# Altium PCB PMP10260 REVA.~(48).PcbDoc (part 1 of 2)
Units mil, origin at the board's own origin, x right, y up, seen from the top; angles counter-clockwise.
Board outline 5118.11 x 4724.41 mil, 4 copper layers (Top Layer, MidLayer1, MidLayer2, Bottom Layer), stack 63.8 mil thick; 175 components, 80 nets, 424 pads, 447 vias.
Unrouted connection lines stored in the file: 1.
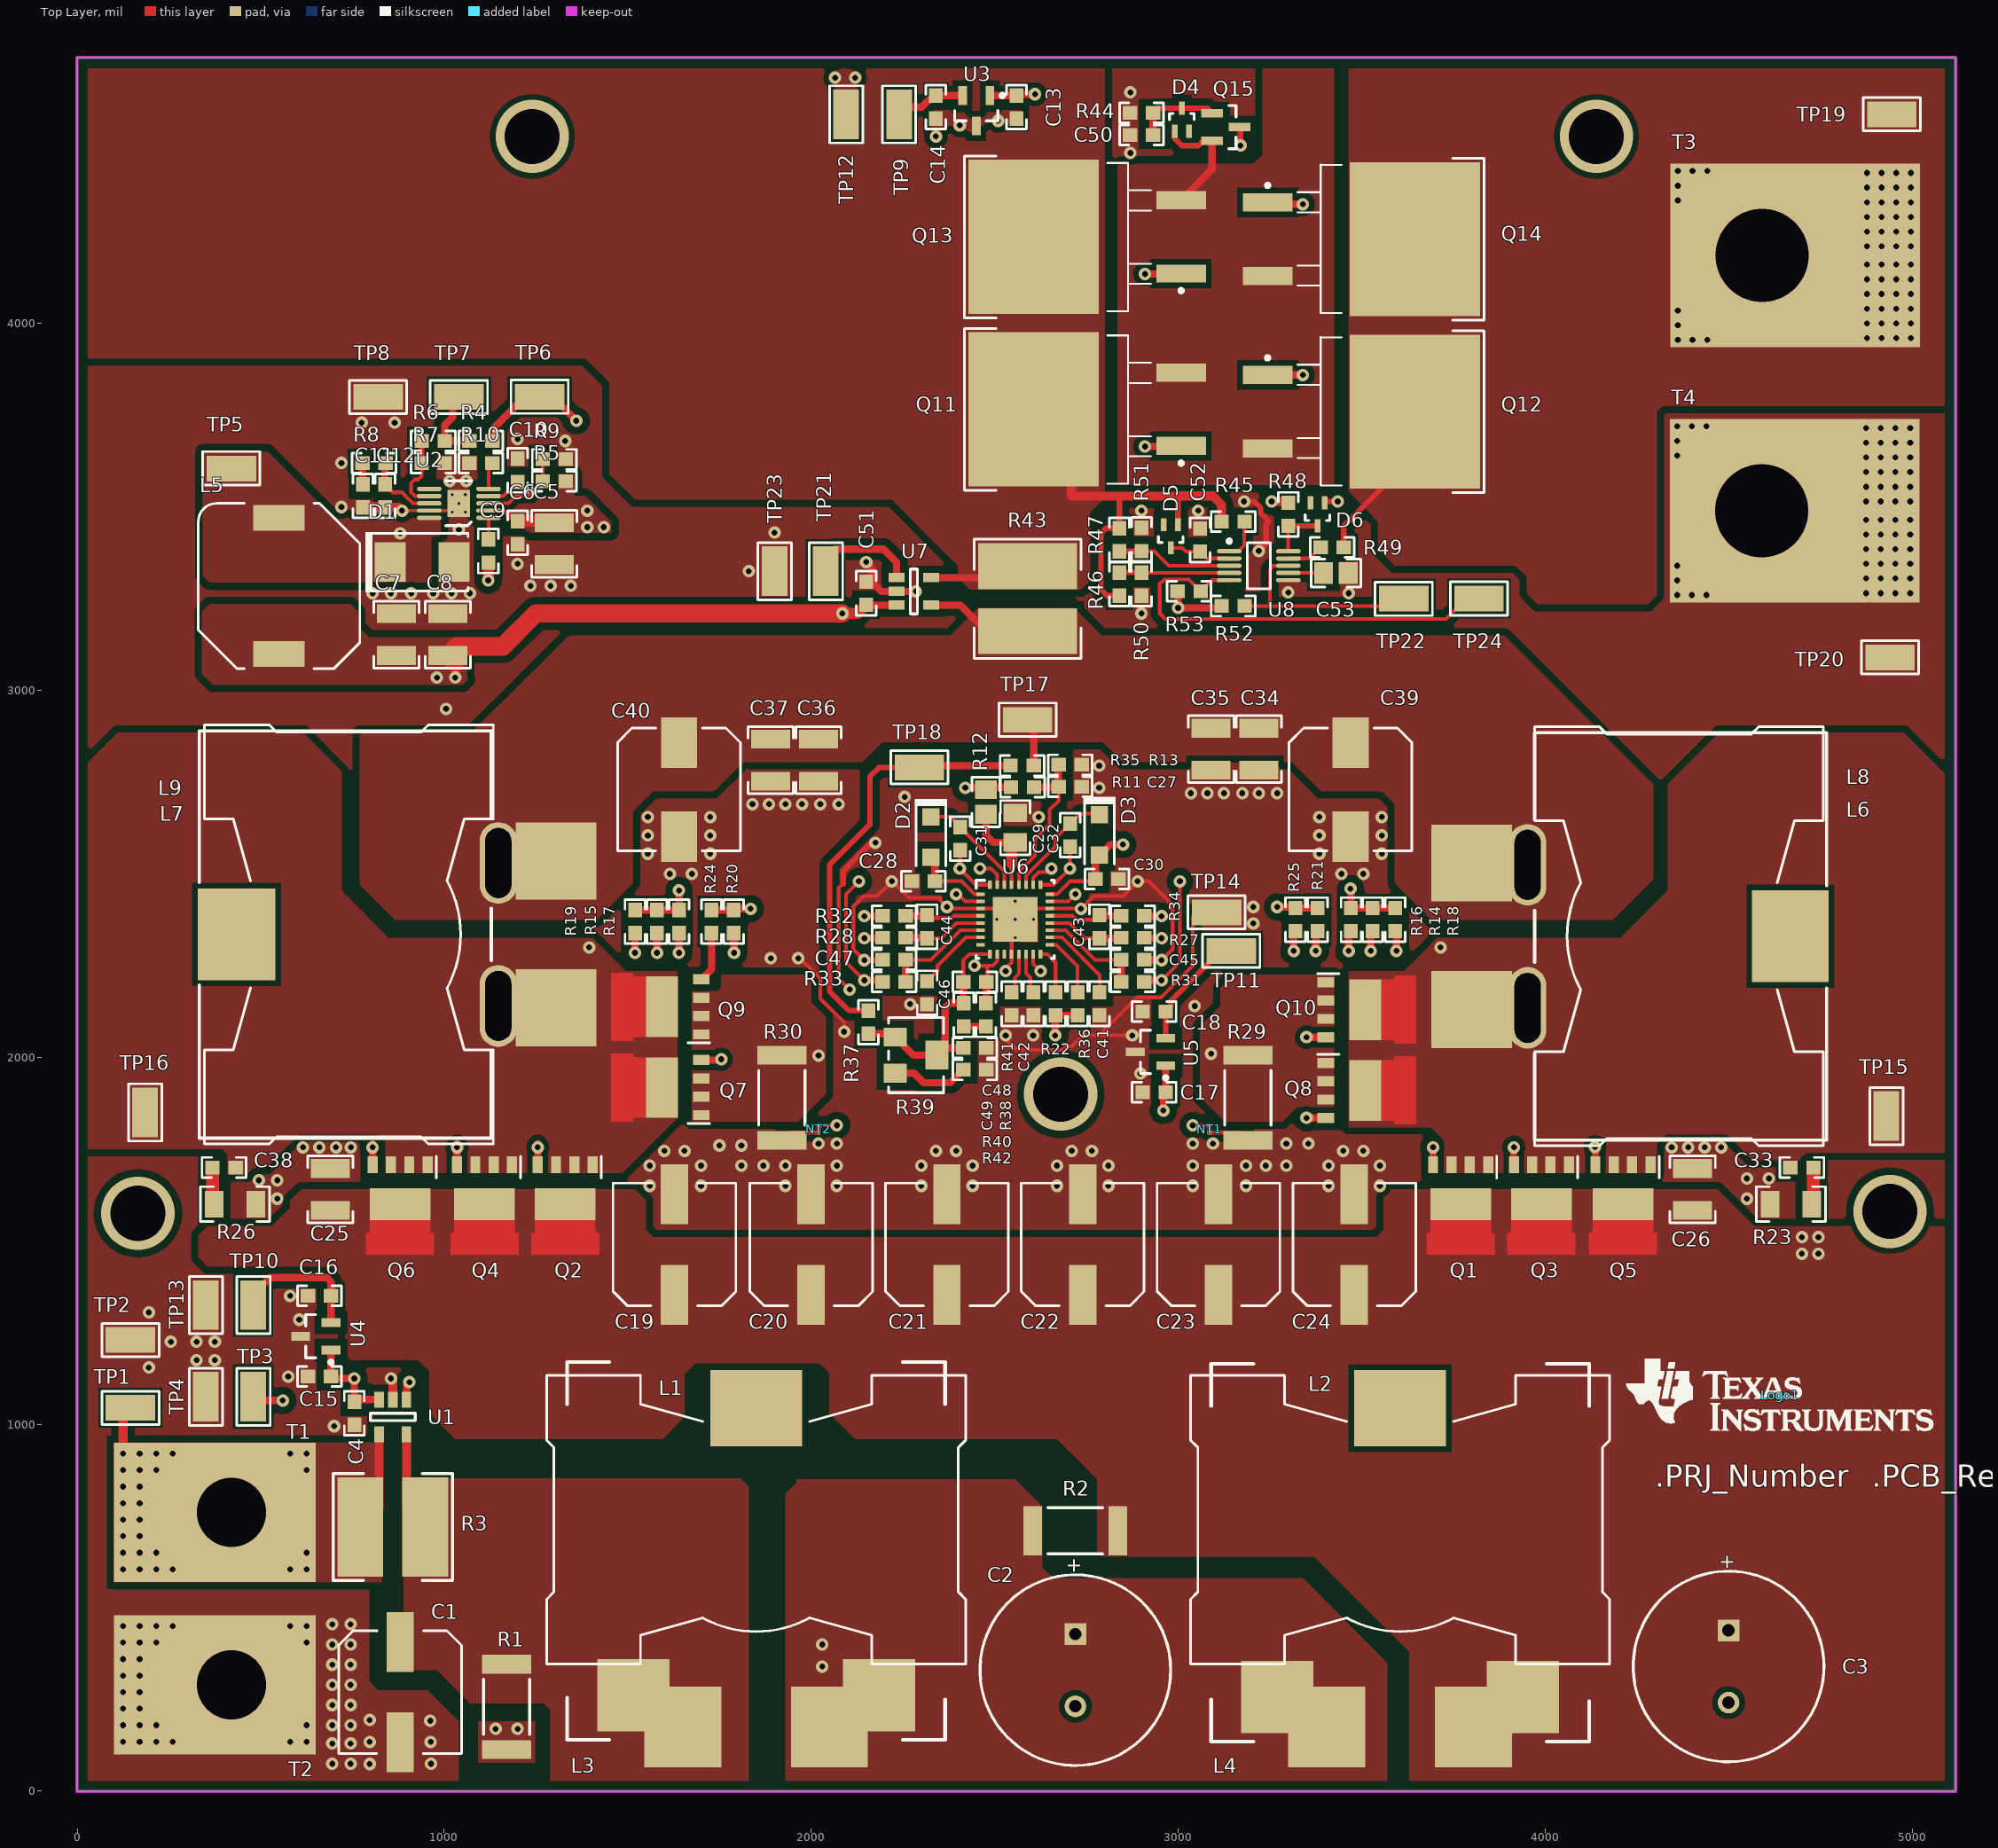
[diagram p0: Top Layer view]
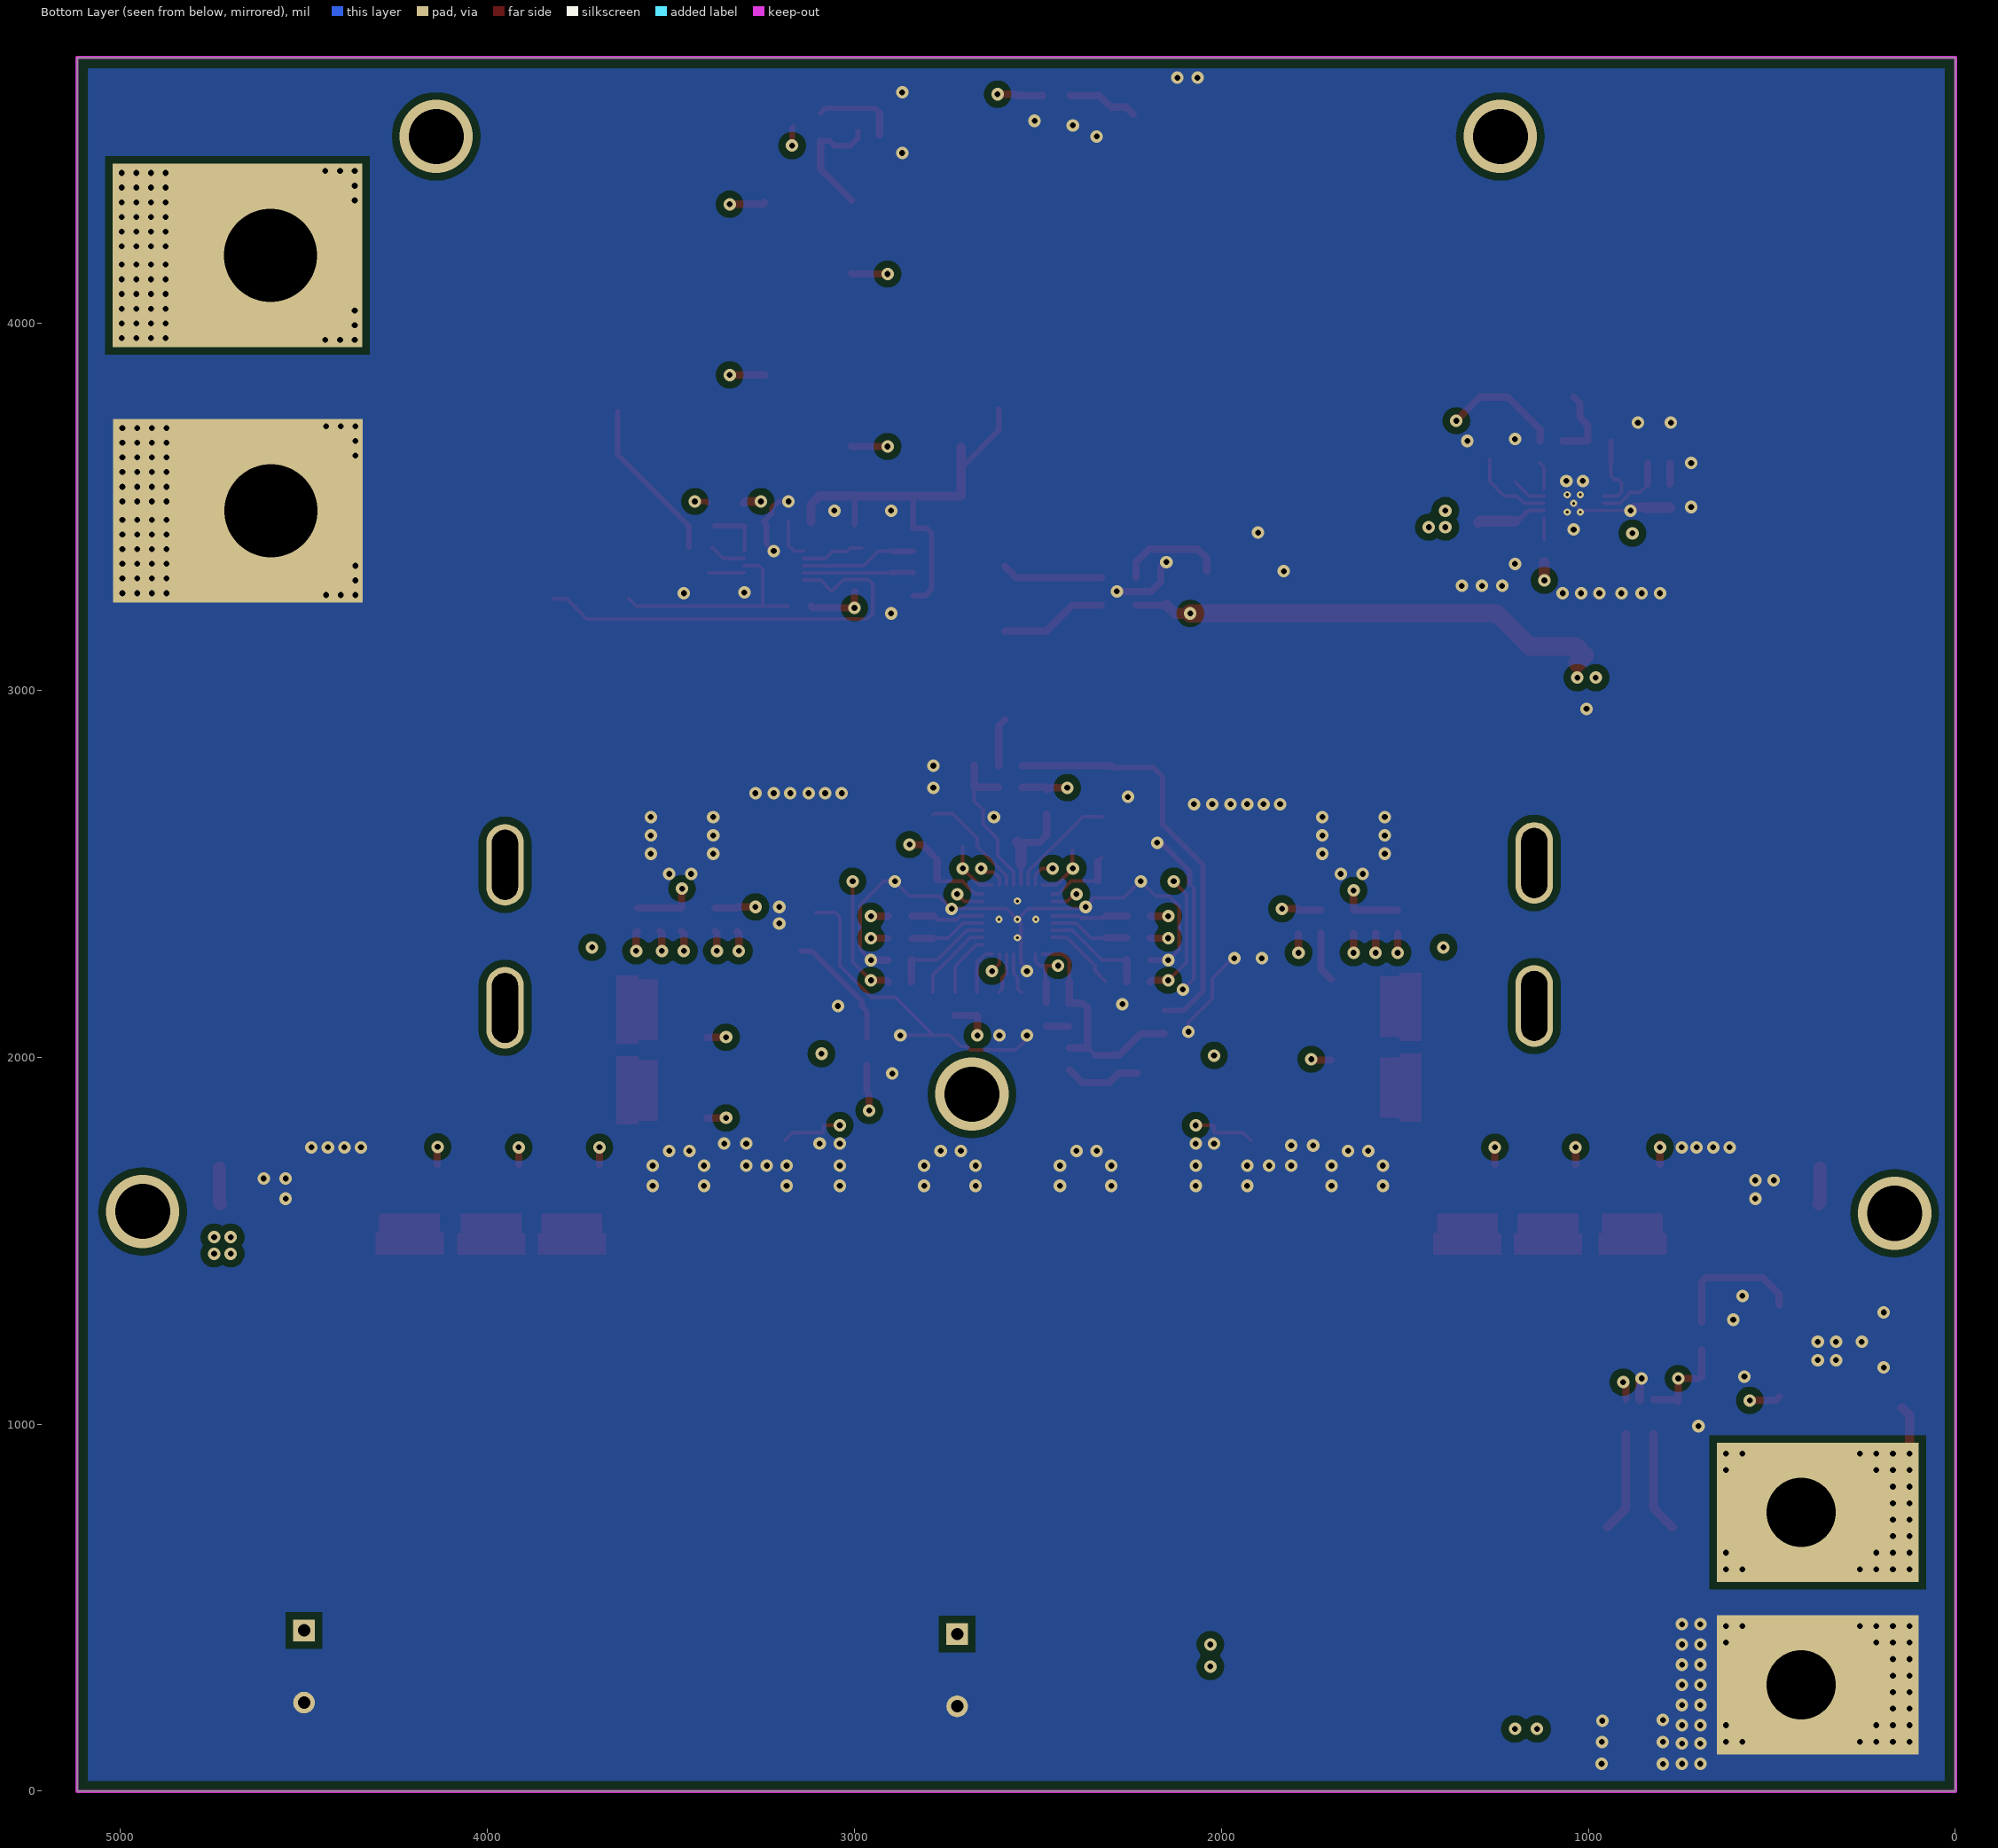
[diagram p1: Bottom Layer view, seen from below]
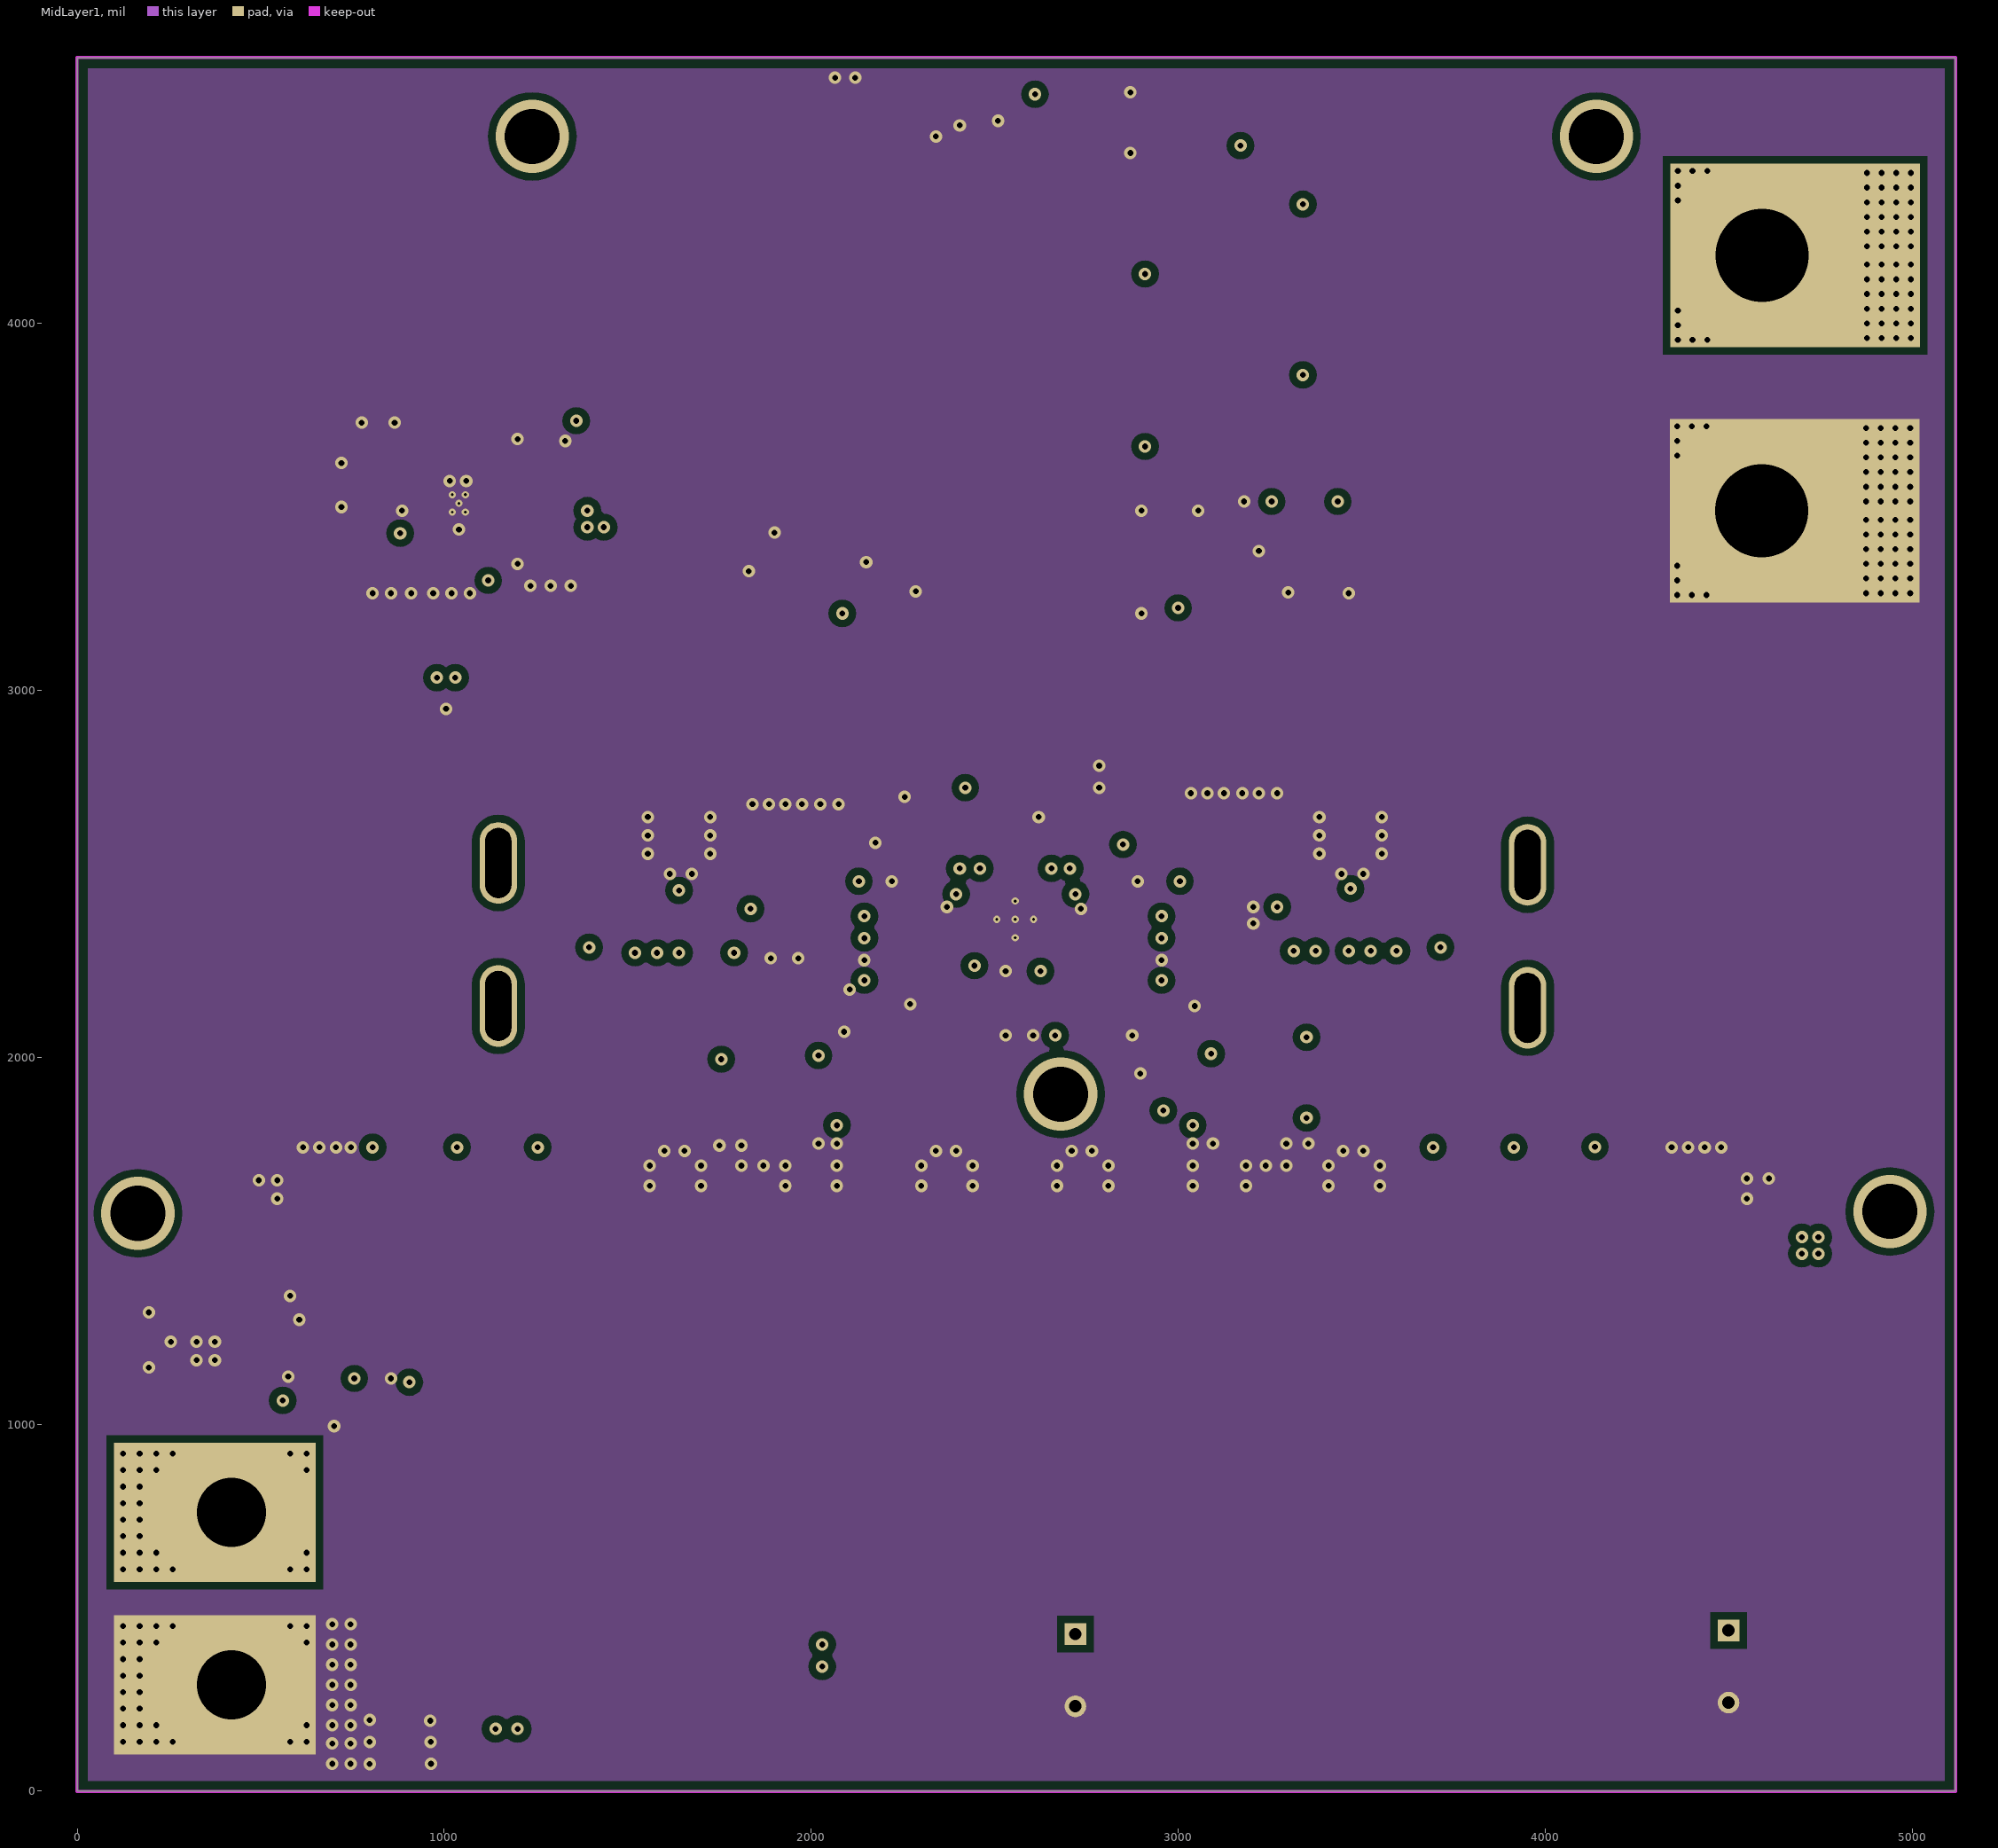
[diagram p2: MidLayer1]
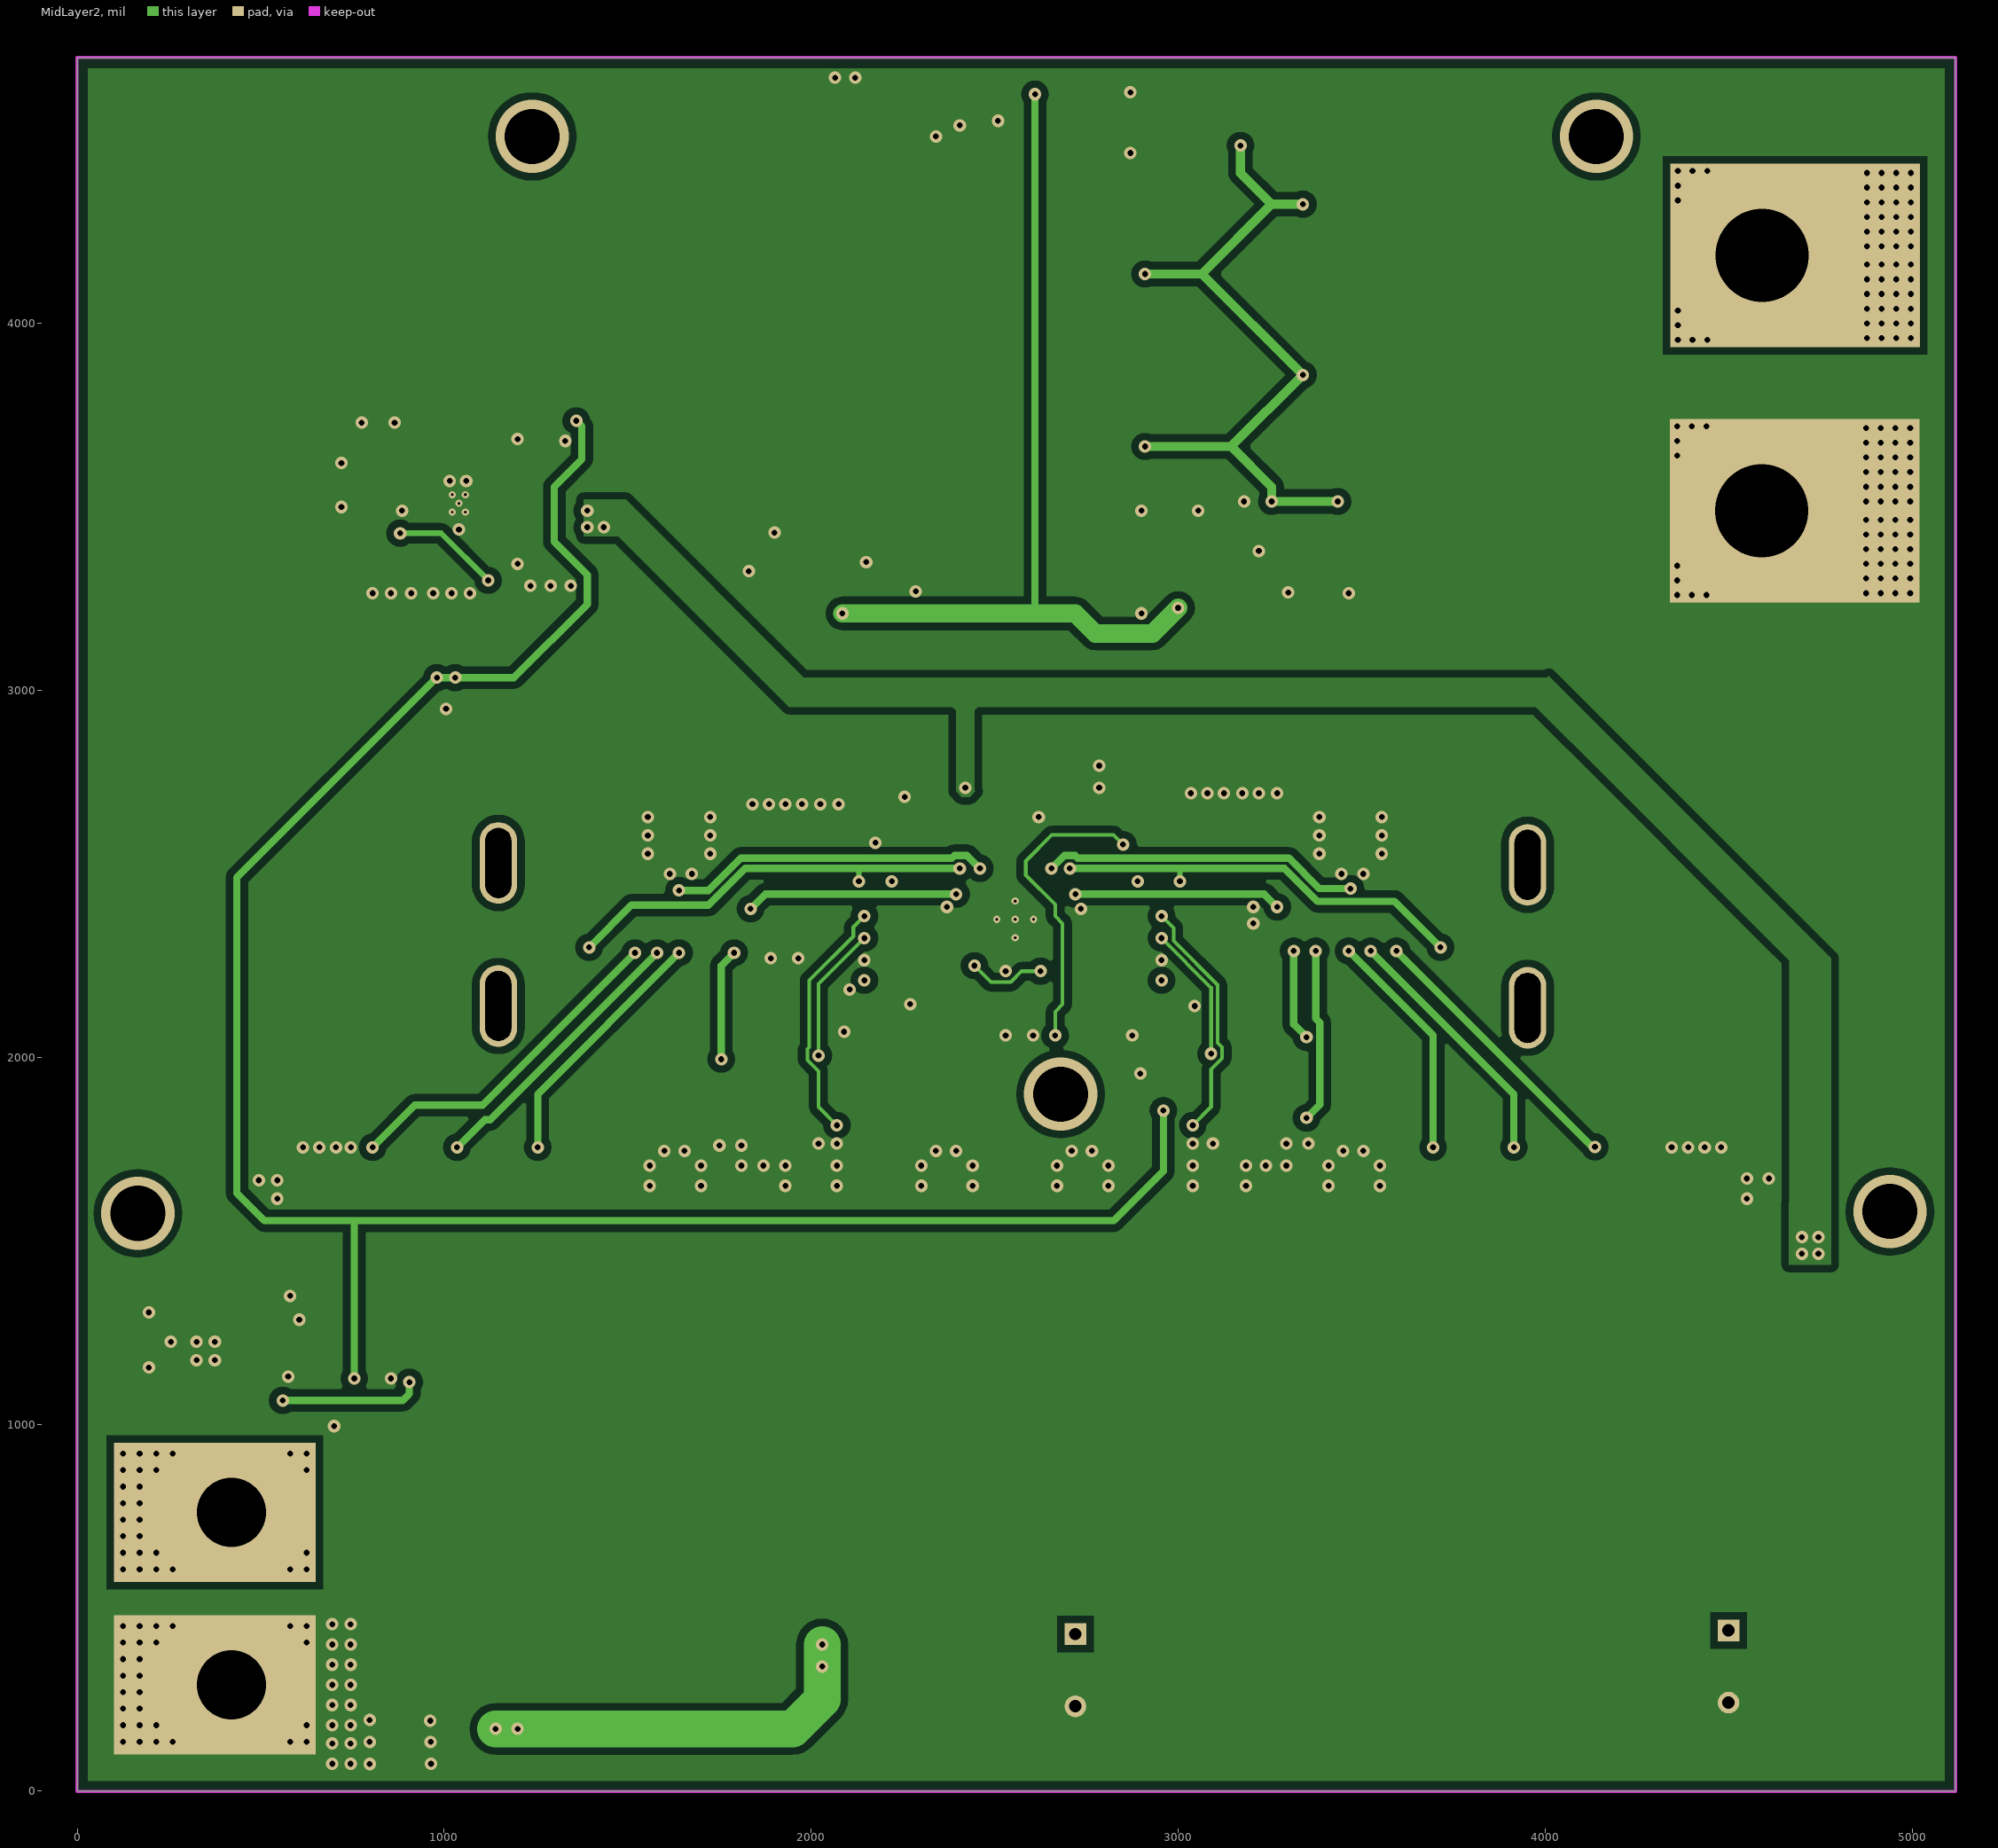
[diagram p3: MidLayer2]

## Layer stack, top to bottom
Top Layer: signal copper 2.8
Dielectric: core 20, FR-4, Dk 4.8
MidLayer1: signal copper 2.8
Dielectric: prepreg 12.6, FR-4, Dk 4.8
MidLayer2: signal copper 2.8
Dielectric: core 20, FR-4, Dk 4.8
Bottom Layer: signal copper 2.8

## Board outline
0,0 5118.11,0 5118.11,4724.41 0,4724.41

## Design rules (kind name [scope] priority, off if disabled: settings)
AcuteAngle [All] p1: minimum=4.50000000000000E+0001 checktracksonly=FALSE
AssemblyTestPointUsage [All] p1: valid=2
Clearance Clearance_BoardEdge_MountingHoles [OnCopper and InComponentClass('Mounting Holes') vs IsKeepOut] p1: gap=40
Clearance Clearance_BoardEdge_Poly [OnCopper and InPoly vs IsKeepOut] p2: gap=25
Clearance Clearance_BoardEdge [OnCopper and Not InComponentClass('Logo') and not InComponentClass('FiducialMark') and not InRegion(1000,500,4000,800) and Not IsKeepout vs IsKeepOut] p3: gap=25
Clearance Clearance_Poly [InPolygon] p4: gap=15
Clearance [All] p5: gap=8
ComponentClearance ComponentClearance_Shunt [InComponentClass('Header') vs InComponentClass('Shunt')] p1: gap=0 collisioncheckmode=3 verticalgap=0 showdistances=FALSE
ComponentClearance ComponentClearance_Logo [InComponentClass('Logo')] p2: gap=20 collisioncheckmode=3 verticalgap=10 showdistances=FALSE
ComponentClearance ComponentClearance_ScrewToNut [(HasFootprint('NY PMS 440 0025 PH')) vs (HasFootprint('Keystone_1902C'))] p3: gap=5 collisioncheckmode=3 verticalgap=10 showdistances=FALSE
ComponentClearance ComponentClearance_MountingHoles [InComponentClass('Mounting Holes')] p4: gap=100 collisioncheckmode=3 verticalgap=100000 showdistances=FALSE
ComponentClearance ComponentClearance_SmallPassives [HasFootprint('0201*') or HasFootprint('0402*') or HasFootprint('0508') or HasFootprint('0603*') or HasFootprint('0612') or HasFootprint('0805*') or HasFootprint('0815*') or HasFootprint('0830*') or HasFootprint('1206*') or HasFootprint('1210*') or HasFootprint('1808*') or HasFootprint('1812*') or HasFootprint('1825*') or HasFootprint('2010*') or HasFootprint('2220*') or HasFootprint('2225*') or HasFootprint('2512*') or HasFootprint('2728*') or HasFootprint('3518*') vs HasFootprint('0201*') or HasFootprint('0402*') or HasFootprint('0508') or HasFootprint('0603*') or HasFootprint('0612') or HasFootprint('0805*') or HasFootprint('0815*') or HasFootprint('0830*') or HasFootprint('1206*') or HasFootprint('1210*') or HasFootprint('1808*') or HasFootprint('1812*') or HasFootprint('1825*') or HasFootprint('2010*') or HasFootprint('2220*') or HasFootprint('2225*') or HasFootprint('2512*') or HasFootprint('2728*') or HasFootprint('3518*')] p5: gap=15 collisioncheckmode=3 verticalgap=10 showdistances=FALSE
ComponentClearance ComponentClearance_THtoSMT [IsThruComponent vs IsSMTComponent] p6: gap=50 collisioncheckmode=3 verticalgap=30 showdistances=FALSE
ComponentClearance ComponentClearance_THtoTH [IsThruComponent vs IsThruComponent] p7: gap=50 collisioncheckmode=3 verticalgap=30 showdistances=FALSE
ComponentClearance [All] p8: gap=25 collisioncheckmode=3 verticalgap=10 showdistances=FALSE
DiffPairsRouting [All] p1: maxlimit=100 minlimit=10 mostfreqgap=10 maxuncoupledlength=1000
FabricationTestPointUsage TestPointUsage [All] p1: valid=2 allowmultiple=FALSE
FabricationTestpoint Testpoint [All] p1: side=3 testpointundercomponent=TRUE minsize=40 maxsize=100 preferedsize=60 minholesize=0 maxholesize=40 preferedholesize=32 testpointgrid=1 allowsidetop=TRUE allowsidebottom=TRUE usegrid=TRUE gridtolerance=0.01
FanoutControl Fanout_LCC [IsLCC] p1: bgadir=Out bgaviamode=Centered fanoutstyle=Auto fanoutdirection=Alternating viagrid=1 // Fanout_LCC (Default Rule)
FanoutControl Fanout_BGA [IsBGA] p2: bgadir=Out bgaviamode=Centered fanoutstyle=Auto fanoutdirection=Alternating viagrid=1 // Fanout_BGA (Default Rule)
FanoutControl Fanout_Default [All] p4: bgadir=Out bgaviamode=Centered fanoutstyle=Auto fanoutdirection=Alternating viagrid=1 // Fanout_Default (Default Rule)
FanoutControl Fanout_Small [(CompPinCount < 5)] p5: bgadir=Out bgaviamode=Centered fanoutstyle=Auto fanoutdirection=OutThenIn viagrid=1 // Fanout_Small (Default Rule)
HoleSize [All] p1: absolutevalues=TRUE maxlimit=251 minlimit=8 maxpercent=80.000 minpercent=20.000
MinimumAnnularRing MinimumAnnularRing_ThermalPadVias [IsVia and InAnyComponent] p1: minimumring=5.91
MinimumAnnularRing [All] p2: minimumring=9
MinimumSolderMaskSliver MinimumSolderMaskSliver_Logo [InComponentClass('Logo') vs InComponentClass('Logo')] p1: minsoldermaskwidth=0.7
MinimumSolderMaskSliver [All] p2: minsoldermaskwidth=3
PlaneClearance [All] p1: clearance=15
PlaneConnect [All] p1: planeconnectstyle=Direct reliefexpansion=10 reliefentries=4 reliefconductorwidth=10 reliefairgap=10
PolygonConnect [All] p1: connectstyle=Direct reliefconductorwidth=10 reliefentries=4 polygonreliefangle="90 Angle" airgapwidth=10
RoomDefinition "PMP10260 REVA SH2" [InComponentClass('PMP10260 REVA SH2')] p1: confinementstyle=ConfineIn formatcopy=TRUE lockcomponents=FALSE outline -692,-1534 1308,-1534 1308,-534 -692,-534
RoutingVias ThermalPadVias [IsVia and InAnyComponent] p1: holewidth=7.87 width=19.68 viastyle="Through Hole" minholewidth=7.87 minwidth=19.68 maxholewidth=12.99 maxwidth=23.62
RoutingVias [All] p2: holewidth=16 width=34 viastyle="Through Hole" minholewidth=7.87 minwidth=26 maxholewidth=40 maxwidth=65
SMDToCorner [All] p1: distance=30000
SilkToSilkClearance [All] p1: silktosilkclearance=0
SilkscreenOverComponentPads [All] p1: minsilkscreentomaskgap=0
SolderMaskExpansion [All] p1: expansion=1.97
Width [All] p1: maxlimit=100 minlimit=6 preferedwidth=10 checkconnectedcopper=TRUE
13 further rules are at their usual default settings.

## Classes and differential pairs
component class "PMP10260 REVA SH3": C50 C51 C52 C53 D4 D5 D6 Q11 Q12 Q13 Q14 Q15 R43 R44 R45 R46 R47 R48 R49 R50 R51 R52 R53 T3 T4 TP19 TP20 TP21 TP22 TP24 U7 U8
component class "PMP10260 REVA SH2": C19 C20 C21 C22 C23 C24 C25 C26 C27 C28 C29 C30 C31 C32 C33 C34 C35 C36 C37 C38 C39 C40 C41 C42 C43 C44 C45 C46 C47 C48 C49 D2 D3 L6 L7 L8 L9 NT1 NT2 Q1 Q2 Q3 Q4 Q5 Q6 Q7 Q8 Q9 Q10 R11 R12 R13 R14 R15 R16 R17 R18 R19 R20 R21 R22 R23 R24 R25 R26 R27 R28 R29 R30 R31 R32 R33 R34 R35 R36 R37 R38 R39 R40 R41 R42 TP15 TP16 TP17 TP18 U6
component class "PMP10260 REVA SH1": C1 C2 C3 C4 C5 C6 C7 C8 C9 C10 C11 C12 C13 C14 C15 C16 C17 C18 D1 L1 L2 L3 L4 Logo1 R1 R2 R3 R4 R5 R6 R7 R8 R9 R10 T1 T2 TP1 TP2 TP3 TP4 TP5 TP6 TP7 TP8 TP9 TP10 TP11 TP12 TP13 TP14 U1 U2 U3 U4 U5
component class Logo: Logo1

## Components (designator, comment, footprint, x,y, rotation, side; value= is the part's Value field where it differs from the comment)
C1 "63SXV33M" SXV_E12 880,270 r270 top
C2 "63ZLH470M12.5X25" ZLH_1250x2500 2720,330 r270 top
C3 "63ZLH470M12.5X25" ZLH_1250x2500 4500,340 r270 top
C4 "C1608X7R1H104K" 0603 755,1030 r270 top
C5 "GRM32ER72A225KA35L" 1210 1300.02,3399.97 r270 top
C6 "GRM188R72A104KA35D" 0603 1200.02,3429.97 r270 top
C7 "C3225X7R1C226M" 1210 869.7,3152.41 r90 top
C8 "C3225X7R1C226M" 1210 1009.7,3152.41 r90 top
C9 "C1608X7R1H104K" 0603 1120.02,3379.97 r90 top
C10 "C1608X7R1H103K" 0603 1200.02,3599.97 r90 top
C11 "C1608C0G1H472J" 0603 778.56,3529.97 r270 top
C12 "" 0603 838.56,3529.97 r270 top
C13 "C1608X7R1H104K" 0603 2560,4590 r270 top
C14 "C1608X7R1E105K080AB" 0603 2340,4590 r270 top
C15 "C1608X7R1H104K" 0603 660,1130 r180 top
C16 "C1608X7R1E105K080AB" 0603 660,1350 r180 top
C17 "C1608X7R1H104K" 0603 2934.68,1905 r180 top
C18 "C1608X7R1E105K080AB" 0603 2934.68,2125 r180 top
C19 "63SXV33M" SXV_E12 1627.32,1490 r90 top
C20 "63SXV33M" SXV_E12 2000,1490 r90 top
C21 "63SXV33M" SXV_E12 2370,1490 r90 top
C22 "63SXV33M" SXV_E12 2740,1490 r90 top
C23 "63SXV33M" SXV_E12 3110,1490 r90 top
C24 "63SXV33M" SXV_E12 3480,1490 r90 top
C25 "GRM32ER72A225KA35L" 1210 690,1640 r90 top
C26 "GRM32ER72A225KA35L" 1210 4402.28,1640.16 r90 top
C27 "C1608C0G1H471J" 0603 2706.06,2737.36 r0 top
C28 "C1608X7R1E105K080AB" 0603 2306.06,2480.51 r180 top
C29 "C2012X7R2A104K" 0805_HV 2556.06,2626.06 r90 top
C30 "C1608X7R1E105K080AB" 0603 2806.06,2486.06 r0 top
C31 "C1608X7R1E105K080AB" 0603 2406.06,2596.06 r270 top
C32 "C1608X7R1E105K080AB" 0603 2706.06,2606.06 r270 top
C33 "C0603C222K5RAC" 0603 4700,1700 r0 top
C34 "GMK325AB7106MM-T" 1210 3220,2840 r270 top
C35 "" 1210 3090,2840 r270 top
C36 "" 1210 2020,2810 r270 top
C37 "GMK325AB7106MM-T" 1210 1890,2810 r270 top
C38 "C0603C222K5RAC" 0603 400,1700 r180 top
C39 "20SVPF390M" SM_RADIAL_8MM 3470,2730 r270 top
C40 "20SVPF390M" SM_RADIAL_8MM 1640,2730 r270 top
C41 "C1608X7R1H104K" 0603 2786.06,2146.06 r90 top
C42 "C0603C474K4RACTU" 0603 2606.06,2146.06 r90 top
C43 "C1608C0G1H102J" 0603 2786.06,2356.06 r90 top
C44 "C1608C0G1H102J" 0603 2316.06,2356.06 r90 top
C45 "C1608C0G1H102J" 0603 2876.06,2266.06 r0 top
C46 "C1608X7R1H104K" 0603 2316.06,2176.06 r270 top
C47 "C1608C0G1H102J" 0603 2226.06,2266.06 r180 top
C48 "C1608C0G1H101J" 0603 2446.06,2206.06 r180 top
C49 "GRM188R71H333KA61D" 0603 2416.06,2116.06 r90 top
C50 "C1608X7R1H103K" 0603 2900.2,4514.07 r180 top
C51 "C1608X7R1H104K" 0603 2150,3265 r90 top
C52 "C1608X7R1H104K" 0603 3060,3410 r90 top
C53 "0805YC274KAT2A" 0805 3430,3320 r0 top
D1 "MBRS1100T3G" SMB 940.02,3349.97 r0 top
D2 "PMEG6010CEH" SOD-123F 2326.06,2600.51 r270 top
D3 "PMEG6010CEH" SOD-123F 2786.06,2606.06 r270 top
D4 "BAS116T-7-F" SOT-523 3010.2,4555.39 r90 top
D5 "BAS116T-7-F" SOT-523 2980,3420 r270 top
D6 "BAS116T-7-F" SOT-523 3380,3480 r270 top
L1 "" SER2918 1850,740 r90 top
L2 "" SER2918 3605,740 r90 top
L3 "PG1096.152NL" IND_PG1096 1850,655 r0 top
L4 "PG1096.152NL" IND_PG1096 3605,650 r0 top
L5 "MSS1048-104MLB" MSS1048 550,3285 r270 top
L6 "" SER29XX 4330,2330 r90 top
L7 "" SER29XX 770,2335 r270 top
L8 "SER2915H-682KL" SER2915 4365,2330 r0 top
L9 "SER2915H-682KL" SER2915 740,2335 r180 top
Logo1 "Texas Instruments" TI_Stacked_Overlay_Small 4640,1080 r0 top
NT1 "Net-Tie" Net-Tie_10mil 3085,1805 r270 top net-tie
NT2 "Net-Tie" Net-Tie_10mil 2020,1805 r90 top net-tie
Q1 "BUK7Y6R0-60EX" LFPAK56 3770,1600 r180 top
Q2 "BUK7Y6R0-60EX" LFPAK56 1329.84,1600 r180 top
Q3 "BUK7Y6R0-60EX" LFPAK56 3990,1600 r180 top
Q4 "BUK7Y6R0-60EX" LFPAK56 1109.84,1600 r180 top
Q5 "BUK7Y6R0-60EX" LFPAK56 4212.28,1600.16 r180 top
Q6 "BUK7Y6R0-60EX" LFPAK56 879.84,1600 r180 top
Q7 "BUK7Y6R0-60EX" LFPAK56 1593.46,1917.72 r90 top
Q8 "BUK7Y6R0-60EX" LFPAK56 3510,1910 r270 top
Q9 "BUK7Y6R0-60EX" LFPAK56 1593.46,2137.72 r90 top
Q10 "BUK7Y6R0-60EX" LFPAK56 3510,2130 r270 top
Q11 "IPB120N04S4-02" DDPAK 2762.09,3766.18 r180 top
Q12 "IPB120N04S4-02" DDPAK 3490,3760 r0 top
Q13 "IPB120N04S4-02" DDPAK 2762.09,4236.18 r180 top
Q14 "IPB120N04S4-02" DDPAK 3490,4230 r0 top
Q15 "MMBT2222A" SOT-23 3130.2,4535.39 r0 top
R1 "CSRN2512FKR200" 2512 1170,230 r270 top
R2 "CSRN2512FKR200" 2512 2720,710 r0 top
R3 "CSS2725FT1L00" CSS2725_0005 860,720 r0 top
R4 "CRCW060349R9FKEA" 0603 1100,3680 r0 top
R5 "CRCW0603178KFKEA" 0603 1300.02,3569.97 r0 top
R6 "CRCW060353K6FKEA" 0603 970.02,3679.65 r0 top
R7 "CRCW060310K2FKEA" 0603 970.02,3619.97 r180 top
R8 "CRCW060388K7FKEA" 0603 808.56,3619.97 r180 top
R9 "CRCW060349K9FKEA" 0603 1300.02,3629.97 r180 top
R10 "CRCW0603237KFKEA" 0603 1100.02,3619.97 r0 top
R11 "CRCW060375K0FKEA" 0603 2576.06,2736.06 r180 top
R12 "CRCW08051R00FKEA" 0805 2476.06,2696.06 r270 top
R13 "CRCW06035K76FKEA" 0603 2706.06,2797.36 r180 top
R14 "CRCW06032R20JNEA" 0603 3530,2375.55 r270 top
R15 "CRCW06032R20JNEA" 0603 1580,2370 r90 top
R16 "CRCW06032R20JNEA" 0603 3471.3,2375.55 r270 top
R17 "CRCW06032R20JNEA" 0603 1640,2370 r90 top
R18 "CRCW06032R20JNEA" 0603 3591.3,2375.55 r270 top
R19 "CRCW06032R20JNEA" 0603 1520,2370 r90 top
R20 "CRCW06032R20JNEA" 0603 1788.7,2370 r90 top
R21 "CRCW06032R20JNEA" 0603 3380,2375.55 r270 top
R22 "CRCW06030000Z0EA" 0603 2666.06,2146.06 r270 top
R23 "CRCW120610R0JNEA" 1206 4670,1600 r0 top
R24 "CRCW06032R20JNEA" 0603 1728.7,2370 r90 top
R25 "CRCW06032R20JNEA" 0603 3320,2375.55 r270 top
R26 "CRCW120610R0JNEA" 1206 430,1600 r180 top
R27 "RC0603FR-07100RL" 0603 2876.06,2326.06 r0 top
R28 "RC0603FR-07100RL" 0603 2226.06,2326.06 r180 top
R29 "ERJ-M1WTF1M0U" 2512 3190,1890 r90 top
R30 "ERJ-M1WTF1M0U" 2512 1920,1890 r90 top
R31 "CRCW0603249KFKEA" 0603 2876.06,2206.06 r0 top
R32 "RC0603FR-07100RL" 0603 2226.06,2386.06 r180 top
R33 "CRCW0603249KFKEA" 0603 2226.06,2206.06 r180 top
R34 "RC0603FR-07100RL" 0603 2876.06,2386.06 r0 top
R35 "CRCW060349R9FKEA" 0603 2575,2795 r0 top
R36 "CRCW06030000Z0EA" 0603 2726.06,2146.06 r90 top
R37 "CRCW060320K0FKEA" 0603 2156.06,2096.06 r90 top
R38 "CRCW060320K0FKEA" 0603 2476.06,2116.06 r270 top
R39 "3224W-2-103E" TRIM_3224W 2286.06,2006.06 r0 top
R40 "CRCW06031K62FKEA" 0603 2446.06,2026.06 r180 top
R41 "CRCW060336K5FKEA" 0603 2546.06,2146.06 r90 top
R42 "CRCW06033K01FKEA" 0603 2446.06,1966.06 r180 top
R43 "CSS2725FTL500" CSS2725_0005 2590,3250 r90 top
R44 "CRCW060310K0FKEA" 0603 2900.2,4574.07 r0 top
R45 "CRCW060313K7FKEA" 0603 3150,3460 r180 top
R46 "CRCW060382K5FKEA" 0603 2840,3290 r270 top
R47 "CRCW060382K5FKEA" 0603 2840,3410.47 r90 top
R48 "CRCW06031K00FKEA" 0603 3300,3480 r270 top
R49 "CRCW060310K0FKEA" 0603 3420,3390 r180 top
R50 "CRCW060316K5FKEA" 0603 2900,3290 r90 top
R51 "CRCW060311K0FKEA" 0603 2900,3411.5 r270 top
R52 "CRCW060310K0FKEA" 0603 3150,3230 r0 top
R53 "CRCW060310K0FKEA" 0603 3030,3270 r0 top
T1 "CB35-36-CY" CB35-36-CY 420,760 r0 top
T2 "CB35-36-CY" CB35-36-CY 420,290 r0 top
T3 "CB70-14-CY" CB70-14-CY 4591.89,4185.55 r180 top
T4 "CB70-14-CY" CB70-14-CY 4590,3490 r180 top
TP1 "5015" Testpoint_Keystone_Miniature 145,1045 r0 top
TP2 "5015" Testpoint_Keystone_Miniature 145,1230 r0 top
TP3 "5015" Testpoint_Keystone_Miniature 480,1075 r90 top
TP4 "5015" Testpoint_Keystone_Miniature 350,1075 r90 top
TP5 "5015" Testpoint_Keystone_Miniature 420,3605 r180 top
TP6 "5015" Testpoint_Keystone_Miniature 1260,3800 r180 top
TP7 "5015" Testpoint_Keystone_Miniature 1040,3800 r0 top
TP8 "5015" Testpoint_Keystone_Miniature 820,3800 r0 top
TP9 "5015" Testpoint_Keystone_Miniature 2240,4570 r270 top
TP10 "5015" Testpoint_Keystone_Miniature 480,1325 r90 top
TP11 "5015" Testpoint_Keystone_Miniature 3145,2290 r180 top
TP12 "5015" Testpoint_Keystone_Miniature 2095,4570 r90 top
TP13 "5015" Testpoint_Keystone_Miniature 350,1325 r90 top
TP14 "5015" Testpoint_Keystone_Miniature 3105,2395 r180 top
TP15 "5015" Testpoint_Keystone_Miniature 4930,1840 r90 top
TP16 "5015" Testpoint_Keystone_Miniature 185,1850 r90 top
TP17 "5015" Testpoint_Keystone_Miniature 2590,2920 r180 top
TP18 "5015" Testpoint_Keystone_Miniature 2295,2790 r180 top
TP19 "5015" Testpoint_Keystone_Miniature 4945,4570 r180 top
TP20 "5015" Testpoint_Keystone_Miniature 4940,3090 r180 top
TP21 "5015" Testpoint_Keystone_Miniature 2040,3325 r90 top
TP22 "5015" Testpoint_Keystone_Miniature 3615,3250 r0 top
TP23 "5015" Testpoint_Keystone_Miniature 1900,3325 r90 top
TP24 "5015" Testpoint_Keystone_Miniature 3820,3250 r180 top
U1 "INA198AIDBV" DBV0005A_N 860,1020 r270 top
U2 "TPS54060DGQ" DGQ0010D_N 1040.02,3509.97 r180 top
U3 "LM50CIM3/NOPB" MF03A_N 2450,4580 r270 top
U4 "LM50CIM3/NOPB" MF03A_N 650,1240 r180 top
U5 "LM50CIM3/NOPB" MF03A_N 2924.68,2015 r180 top
U6 "LM5119PSQ/NOPB" RTV0032A 2556.06,2376.06 r0 top
U7 "INA198AIDBV" DBV0005A_N 2280,3270 r0 top
U8 "LM5060Q1MM/NOPB" MUB10A_N 3220,3340 r0 top

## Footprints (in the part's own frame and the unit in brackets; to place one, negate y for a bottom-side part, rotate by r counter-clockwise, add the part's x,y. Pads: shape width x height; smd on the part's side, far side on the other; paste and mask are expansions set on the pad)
0603 [mm] "0603 from SM-752 data"
  rect 1x0.95 smd: 1(-0.8,0) 2(0.8,0)
  silkscreen extent -1.52,-0.69 1.52,0.69, body extent -0.87,-0.47 0.87,0.47, height 0.85
0805 [mm] "0805 from SM-752 data"
  rect 1.3x1.5 smd: 1(-0.85,0) 2(0.85,0)
  silkscreen extent -1.72,-0.97 1.72,0.97, body extent -1.1,-0.72 1.1,0.72, height 1.1
0805_HV [mil] "0805 with 30mil clearance between pads"
  rect 50x63 smd: 1(-40,0) 2(40,0)
  silkscreen extent -74,-40 74,40, body extent -43,-29 43,29, height 43
1206 [mm] "1206 from SM-752 data"
  rect 1.3x1.85 smd: 1(-1.45,0) 2(1.45,0)
  silkscreen extent -2.4,-1.21 2.4,1.21, body extent -1.7,-0.9 1.7,0.9, height 1.35
1210 [mm] "1210 from SM-752 data"
  rect 1.3x2.7 smd: 1(-1.45,0) 2(1.45,0)
  silkscreen extent -2.32,-1.57 2.32,1.57, body extent -1.7,-1.35 1.7,1.35, height 1.35
2512 [mm] "Chip Resistor, Body 6.3x3.2mm, IPC Medium Density"
  rect 1.3x3.4 smd: 1(-2.95,0) 2(2.95,0)
  silkscreen extent -1.9,-1.6 1.9,1.6, body extent -3.22,-1.67 3.22,1.67, height 0.71
CB35-36-CY [mil] "Terminal 50A Lug"
  rect 550x380 hole 188 copper offset -45,0 paste-190: 1(0,0)
  body extent -960,-189 230,191, height 614
CB70-14-CY [mil] "Terminal 90A Lug"
  rect 680x500 hole 254 copper offset -90,0 paste-250: 1(0,0)
  body extent -1300,-260 250,260, height 714
CSS2725_0005 [mm] "STACKPOLE ELECTRONICS"
  rect 3.18x6.86 smd: 1(-2.25,0) 2(2.25,0)
  silkscreen extent -4.13,-3.7 4.13,3.7, body extent -3.53,-3.35 3.53,3.35, height 1.24
DBV0005A_N [mm] "SOT23, 5-Leads, Body 2.9x1.6mm, Pitch 0.95mm, Lead Span 2.8mm, IPC Medium Density"
  rect 1.1x0.65 smd: 1(-1.2,0.95) 2(-1.2,0) 3(-1.2,-0.95) 4(1.2,-0.95) 5(1.2,0.95)
  silkscreen extent -0.25,-1.55 0.25,1.55, body extent -1.42,-1.46 1.42,1.46, height 1.08
DDPAK [mil] "D2-PAK, 3-Pads, Body 9.7x10.4mm (max), TO-263AB, using Vishay Silionix recommended pad sizes"
  rect 135x49.49 smd: 1(-246.06,100) 3(-246.06,-100)
  rect 355x420 smd paste-181.1: 4(155.51,0)
  silkscreen extent -251,-220 344,220, body extent -295,-202 324,202, height 180
DGQ0010D_N [mm] "TSSOP, 10-Leads, Body 3x3mm, Pitch 0.5mm, Thermal Pad 1.88x1.57mm, IPC Medium Density"
  oval 1.7x0.3 smd: 1(-2.05,1) 2(-2.05,0.5) 3(-2.05,0) 4(-2.05,-0.5) 5(-2.05,-1) 6(2.05,-1) 7(2.05,-0.5) 8(2.05,0) 9(2.05,0.5) 10(2.05,1)
  rect 1.57x1.88 smd: 11(0,0)
  silkscreen extent -0.9,-1.55 0.9,1.55, body extent -1.55,-1.55 1.55,1.55, height 1.1
IND_PG1096 [mm] "PULSE"
  rect 5x5 smd: 1(-8.5,-10) 2(8.5,-10) 3(0,10)
  silkscreen extent -13.08,-13.08 13.08,13.08, body extent -13,-13 13,13, height 14.51
LFPAK56 [mm] "NXP Semiconductor"
  rect 0.7x1.15 smd paste-0.05: 1(-1.905,-2.725) 2(-0.635,-2.725) 3(0.635,-2.725) 4(1.905,-2.725)
  rect 4.2x2.2 smd paste-1.52: 5(0,0)
  Top Layer region: -2.1,0.65 2.1,0.65 2.1,2 -2.1,2
  Top Layer region: -2.1,1.8 -2.1,2 -2.35,2 -2.35,3.5 2.35,3.5 2.35,2 2.1,2 2.1,1.8
  silkscreen extent -2.5,-3.3 -2.5,-1.8, body extent -2.43,-3.14 2.47,3.29, height 1.18
MF03A_N [mm] "SOT23, 3-Leads, Body 2.9x1.3mm, Pitch 0.95mm, Lead Span 2.4mm, IPC Medium Density"
  rect 1.3x0.6 smd: 1(-1.05,0.95) 2(-1.05,-0.95) 3(1.05,0)
  silkscreen extent -1.17,-1.5 0.7,1.93, body extent -0.7,-1.5 0.7,1.5, height 1.12
MSS1048 [mm] "Coilcraft recommended land pattern Document 462-2 Revised 06/09/09"
  rect 1.78x3.56 smd: 1(-4.7,0) 2(4.7,0)
  silkscreen extent -5.72,-5.59 5.72,5.59, body extent -5.15,-5.1 5.15,5.1, height 5.12
MUB10A_N [mm] "TSSOP, 10-Leads, Body 3x3mm, Pitch 0.5mm, IPC Medium Density"
  oval 1.7x0.3 smd: 1(-2.05,1) 2(-2.05,0.5) 3(-2.05,0) 4(-2.05,-0.5) 5(-2.05,-1) 6(2.05,-1) 7(2.05,-0.5) 8(2.05,0) 9(2.05,0.5) 10(2.05,1)
  silkscreen extent -2.17,-1.6 0.8,1.82, body extent -1.6,-1.6 1.6,1.6, height 1.09
Net-Tie_10mil [mil] "10mil net tie, no solder mask opening, no solder paste"
  rect 10x10 smd paste-5 mask-5: 1(-10,0) 2(10,0)
  Top Layer region: -6,5 6,5 6,-5 -6,-5
RTV0032A [mm] "QFN, 32-Leads, Body 5x5mm, Pitch 0.5mm"
  rect 0.6x0.25 smd: 1(-2.4,1.75) 2(-2.4,1.25) 3(-2.4,0.75) 4(-2.4,0.25) 5(-2.4,-0.25) 6(-2.4,-0.75) 7(-2.4,-1.25) 8(-2.4,-1.75) 17(2.4,-1.75) 18(2.4,-1.25) 19(2.4,-0.75) 20(2.4,-0.25) 21(2.4,0.25) 22(2.4,0.75) 23(2.4,1.25) 24(2.4,1.75)
  rect 0.25x0.6 smd: 9(-1.75,-2.4) 10(-1.25,-2.4) 11(-0.75,-2.4) 12(-0.25,-2.4) 13(0.25,-2.4) 14(0.75,-2.4) 15(1.25,-2.4) 16(1.75,-2.4) 25(1.75,2.4) 26(1.25,2.4) 27(0.75,2.4) 28(0.25,2.4) 29(-0.25,2.4) 30(-0.75,2.4) 31(-1.25,2.4) 32(-1.75,2.4)
  rect 3.1x3.1 smd paste-1.55: 33(0,0)
  silkscreen extent -2.7,-2.7 2.7,2.7, body extent -2.55,-2.55 2.55,2.55, height 0.81
SER29XX [mm] "COILCRAFT"
  oval 5.65x2.6 hole 1.8 slot 4.85 at 0 deg: 1(-4.95,9.59) 2(4.95,9.59)
  rect 6.35x5.28 smd: 3(0,-8.59)
  silkscreen extent -14.1,-11.1 14.1,9.1, body extent -14,-11 14,10.39, height 20
SER2915 [mm] "Coilcraft recommended land pattern.  Document 644-2, rev 12/12/08"
  rect 5.59x5.33 smd: 1(-14.355,5.075) 2(-14.355,-5.075)
  rect 5.28x6.35 smd: 3(7.72,0)
  silkscreen extent -10,-14.5 10,14.5, body extent -16.8,-13.95 11.03,13.95, height 15.36
SER2918 [mm] "Coilcraft recommended land pattern.  Document 644-2, rev 12/12/08"
  rect 5.59x5.33 smd: 1(-14.355,5.075) 2(-14.355,-5.075)
  rect 5.28x6.35 smd: 3(7.72,0)
  silkscreen extent -10,-14.5 10,14.5, body extent -16.8,-13.95 11.03,13.95, height 17.78
SM_RADIAL_8MM [mm] "Nichicon 8x10"
  rect 3.5x2.5 smd: 1(-3.25,0) 2(3.25,0)
  silkscreen extent -4.25,-4.25 4.25,4.25, body extent -4.26,-4.26 4.26,4.26, height 10.5
SMB [mil] "Molded Diode, 2-Leads, Body 5.4x3.6mm, IPC Medium Density, based on OnSemi component dimensions"
  rect 85x107.99 smd: 1(-87.01,0) 2(87.01,0)
  silkscreen extent -155,-82 125,82, body extent -106,-71 106,71, height 91
SOD-123F [mm] "NXP recommended land pattern"
  rect 1.2x1.2 smd paste-0.05: 1(-1.4,0) 2(1.4,0)
  silkscreen extent -2.64,-1.12 2.01,1.12, body extent -1.8,-0.85 1.8,0.85, height 1.2
SOT-23 [mm] "SOT23, 3-Leads, Body 2.9x1.3mm, Pitch 0.95mm, Lead Span 2.5mm, IPC Medium Density"
  rect 1.5x0.6 smd: 1(-0.95,0.95) 2(-0.95,-0.95) 3(0.95,0)
  silkscreen extent 0.2,-1.5 0.7,1.5, body extent -1.16,-1.45 1.21,1.45, height 1
SOT-523 [mm] "From Diodes Inc datasheet component parameters"
  rect 0.9x0.4 smd: 1(-0.8,0.5) 2(-0.8,-0.5) 3(0.8,0)
  silkscreen extent 0.02,-0.85 0.42,0.85, body extent -0.8,-0.8 0.8,0.8, height 0.79
SXV_E12 [mm] "OS-CON  8x10"
  rect 4.15x1.9 smd: 1(-3.475,0) 2(3.475,0)
  silkscreen extent -4.25,-4.25 4.25,4.25, body extent -4.26,-4.26 4.26,4.26, height 12
Testpoint_Keystone_Miniature [mil] "Miniature SMT test point"
  rect 135x70 smd: 1(0,0)
  silkscreen extent -78,-46 78,45, body extent -52,-20 52,20, height 61
TI_Stacked_Overlay_Small [mil]
  silkscreen extent -418,-98 418,98
TRIM_3224W [mm] "BOURNS"
  rect 1.6x1.3 smd: 1(-1.45,1.25) 3(-1.45,-1.25)
  rect 1.6x2 smd: 2(1.45,0)
  silkscreen extent -1.9,-2.6 1.9,2.6, body extent -1.8,-2.5 1.8,2.5, height 5.31
ZLH_1250x2500 [mm] "Rubycon"
  rect 1.5x1.5 hole 0.85: 1(-2.5,0)
  round 1.5 hole 0.85: 2(2.5,0)
  silkscreen extent -6.6,-6.6 6.6,6.6, body extent -6.45,-6.49 6.49,6.49, height 26.51

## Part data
C1 C19 C20 C21 C22 C23 C24: "CAP, OS-CON, 33uF, 63V, +/-20%, 0.025 ohm, 8.0x11.9mm SMD"
C2 C3: "CAP, AL, 470uF, 63V, +/-20%, 0.043 ohm, TH"
C4 C9 C13 C15 C17 C41 C46 C51 C52: "CAP, CERM, 0.1uF, 50V, +/-10%, X7R, 0603"
C5 C25 C26: "CAP, CERM, 2.2uF, 100V, +/-10%, X7R, 1210"
C6: "CAP, CERM, 0.1uF, 100V, +/-10%, X7R, 0603"
C7 C8: "CAP, CERM, 22uF, 16V, +/-20%, X7R, 1210"
C10 C50: "CAP, CERM, 0.01uF, 50V, +/-10%, X7R, 0603"
C11: library part C1608C0G1H332J, "CAP, CERM, 4700pF, 50V, +/-5%, C0G/NP0, 0603"
C12: library part C1608X7R1H104K, "CAP, open, 0603"
C14 C16 C18 C28 C30 C31 C32: "CAP, CERM, 1uF, 25V, +/-10%, X7R, 0603"
C27: "CAP, CERM, 470pF, 50V, +/-5%, C0G/NP0, 0603"
C29: "CAP, CERM, 0.1uF, 100V, +/-10%, X7R, 0805"
C33 C38: "CAP, CERM, 2200pF, 50V, +/-10%, X7R, 0603"
C34 C37: "CAP, CERM, 10uF, 35V, +/-20%, X7R, 1206"
C35 C36: library part C3225X7R1H335M, "CAP, CERM, open, 1210"
C39 C40: library part 20SVP100M, "CAP, OS-CON, 390uF, 20V, +/-20%, 0.014 ohm, 8x10 SMD"
C42: "CAP, CERM, 0.47uF, 16V, +/-10%, X7R, 0603"
C43 C44 C45 C47: "CAP, CERM, 1000pF, 50V, +/-5%, C0G/NP0, 0603"
C48: "CAP, CERM, 100pF, 50V, +/-5%, C0G/NP0, 0603"
C49: "CAP, CERM, 0.033uF, 50V, +/-10%, X7R, 0603"
C53: "CAP, CERM, 0.27uF, 16V, +/-10%, X7R, 0805"
D1: "Diode, Schottky, 100V, 1A, SMB"
D2 D3: library part PMEG6010CEH,115, "Diode, Schottky, 60V, 1A, SOD-123F"
D4 D5 D6: "Diode, Switching, 85V, 0.215A, SOT-523"
L1 L2: library part SER2918H-332KL, "Inductor, open, SMD"
L3 L4: library part PG1096.252NL, "Inductor, Shielded E Core, Ferrite, 1.5uH, 47A, 0.00085 ohm, SMD"
L5: "Inductor, Shielded Drum Core, Ferrite, 100uH, 1.36A, 0.25 ohm, SMD"
L6 L7: library part SER29XX, "Inductor, open, TH"
L8 L9: "Inductor, Shielded E Core, Ferrite, 6.8uH, 30A, 0.00186 ohm, SMD"
Logo1: library part TI_Logo, "Texas Instrument Corporate Signature"
NT1 NT2: "Single point connection between nets."
Q1 Q2 Q3 Q4 Q5 Q6 Q7 Q8 Q9 Q10: "MOSFET, N-CH, 60V, 100A, SOT669"
Q11 Q12 Q13 Q14: library part IPB100N10S3-05, "MOSFET, N-CH, 40V, 120A, DDPAK"
Q15: library part "MMBT2222A, Fairchild Semiconductor", "Transistor, NPN, 40V, 0.15A, SOT-23"
R1 R2: "RES, 0.2 ohm, 1%, 2W, 2512"
R3: library part CSS2725FTL500, "RES, 0.001 ohm, 1%, 4W, RES_2725"
R4 R35: "RES, 49.9 ohm, 1%, 0.1W, 0603"
R5: "RES, 178k ohm, 1%, 0.1W, 0603"
R6: "RES, 53.6k ohm, 1%, 0.1W, 0603"
R7: "RES, 10.2k ohm, 1%, 0.1W, 0603"
R8: "RES, 88.7k ohm, 1%, 0.1W, 0603"
R9: "RES, 49.9k ohm, 1%, 0.1W, 0603"
R10: "RES, 237k ohm, 1%, 0.1W, 0603"
R11: "RES, 75.0k ohm, 1%, 0.1W, 0603"
R12: "RES, 1.00 ohm, 1%, 0.125W, 0805"
R13: "RES, 5.76k ohm, 1%, 0.1W, 0603"
R14 R15 R16 R17 R18 R19 R20 R21 R24 R25: "RES, 2.2 ohm, 5%, 0.1W, 0603"
R22 R36: "RES, 0 ohm, 5%, 0.1W, 0603"
R23 R26: "RES, 10 ohm, 5%, 0.25W, 1206"
R27 R28 R32 R34: "RES, 100 ohm, 1%, 0.1W, 0603"
R29 R30: library part CSRN2512FKR200, "RES, 0.001ohm, 1%, 2W, 2512"
R31 R33: "RES, 249k ohm, 1%, 0.1W, 0603"
R37 R38: "RES, 20.0k ohm, 1%, 0.1W, 0603"
R39: "TRIMMER, 10K, 0.25W, SMD"
R40: "RES, 1.62k ohm, 1%, 0.1W, 0603"
R41: "RES, 36.5k ohm, 1%, 0.1W, 0603"
R42: "RES, 3.01k ohm, 1%, 0.1W, 0603"
R43: "RES, 0.0005 ohm, 1%, 4W, RES_2725"
R44 R49 R52 R53: "RES, 10.0k ohm, 1%, 0.1W, 0603"
R45: "RES, 13.7k ohm, 1%, 0.1W, 0603"
R46 R47: "RES, 82.5k ohm, 1%, 0.1W, 0603"
R48: "RES, 1.00k ohm, 1%, 0.1W, 0603"
R50: "RES, 16.5k ohm, 1%, 0.1W, 0603"
R51: "RES, 11.0k ohm, 1%, 0.1W, 0603"
T1 T2: "Terminal 50A Lug"
T3 T4: "Terminal 90A Lug"
TP1 TP2 TP3 TP4 TP5 TP6 TP7 TP8 TP9 TP10 TP11 TP12 TP13 TP14 TP15 TP16 TP17 TP18 TP19 TP20 TP21 TP22 TP23 TP24: "Test Point, Miniature, SMT"
U1 U7: "CURRENT SHUNT MONITOR -16V to +80V Common-Mode Range, DBV0005A"
U2: "Buck Inverting Buck-Boost Step Down Regulator with 3.5 to 60 V Input and 0.8 to 58 V Output, -40 to 150 degC, 10-Pin MSOP-PowerPAD (DGQ), Green (RoHS & no Sb/Br)"
U3 U4 U5: "Single-Supply Centigrade Temperature Sensor, 3-pin SOT-23, Pb-Free"
U6: "LM5119/LM5119Q Wide Input Range Dual Synchronous Buck Controller, RTV0032A"
U8: "High-Side Protection Controller with Low Quiescent Current, 10-pin MSOP, Pb-Free"

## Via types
v1: diameter 34, hole 16, Top Layer to Bottom Layer, 260 vias
v2: diameter 32, hole 16, Top Layer to Bottom Layer, 172 vias
v3: diameter 19.68, hole 7.87, Top Layer to Bottom Layer, 10 vias
v4: diameter 200, hole 150, Top Layer to Bottom Layer, 5 vias

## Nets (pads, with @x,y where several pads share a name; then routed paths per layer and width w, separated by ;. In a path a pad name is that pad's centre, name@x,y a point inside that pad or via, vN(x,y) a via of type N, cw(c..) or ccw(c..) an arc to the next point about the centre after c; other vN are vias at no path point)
COMP: C48.1 R38.1 U6.10 U6.15 | length 456.4
  Top Layer w10: v1(2445,2250) 2480,2250 ; R38.1@2476.06,2147.56 R38.1@2477.56,2149.06 ; C48.1@2477.56,2206.06 2480,2208.5 2480,2250 ; U6.10@2506.85,2281.57 2506.85,2261.85 2495,2250 2480,2250 ; U6.15@2605.28,2281.57 2605.28,2254.72 v1(2625,2235)
  Top Layer w20: R38.1@2477.56,2149.06 C48.1@2477.56,2206.06
  MidLayer2 w10: v1(2445,2250) 2490,2205 2543.98,2205 2573.98,2235 v1(2625,2235)
GND: C1.2 C2.2 C3.2 C4.2 C5.2 C6.2 C7.2 C8.2 C10.2 C11.2 C12.2 C13.2 C14.2 C15.2 C16.2 C17.2 C18.2 C19.2 C20.2 C21.2 C22.2 C23.2 C24.2 C25.2 C26.2 C27.2 C28.2 C29.2 C30.2 C34.2 C35.2 C36.2 C37.2 C39.2 C40.2 C41.1 C42.1 C45.2 C46.2 C47.2 C50.2 C51.2 C52.2 C53.2 D1.2 NT1.2 NT2.1 R7.1 R9.1 R10.1 R13.1 R23.1 R26.1 R29.1 R30.1 R40.1 R41.1 R42.1 R44.1 R50.1 R51.1 T2.1 T4.1 TP2.1 TP4.1 TP8.1 TP12.1 TP13.1 TP14.1 TP20.1 TP23.1 U1.2 U2.9 U2.11 U3.3 U4.3 U5.3 U6.3 U6.12 U6.22 U6.33 U7.2 U8.6 | length 4154.4
  Top Layer w8: v1@876.53,3498.47 884.72,3490.28 U2.9@959.31,3490.28 1020.33,3490.28 v3(1040.02,3509.97)
  Top Layer w10: R30.1@1920,1773.86 1941.14,1795 NT2.1@2020,1795 ; v1(1965,2270) 1970,2270 2025,2215 2025,2160 2090,2095 v1(2090,2070) ; 2086.98,2473.02 2075,2461.05 2075,2215 v1(2105,2185) ; v1(2145,2265) 2115,2295 2115,2411.3 2143.7,2440 2180,2440 v1(2220,2480) 2221.97,2480 2266.97,2435 2350,2435 2352,2433 2352,2428 v1(2370,2410) 2374.41,2405.59 U6.3@2461.57,2405.59 2526.54,2405.59 v3(2556.06,2376.06) ; v1@2530,2050 2560,2020 2685,2020 2695,2030 2710,2030 2740,2060 2785,2060 ; v1(2530,2235) 2530,2242.56 2546.22,2258.78 U6.12@2546.22,2281.57 2546.22,2366.22 v3(2556.06,2376.06) ; v1@2734.41,2405.59 U6.22@2650.55,2405.59 2585.59,2405.59 v3(2556.06,2376.06) ; v1(2735,2405) 2770,2440 2850,2440 v1(2890,2480) 2920,2480 2985,2415 2985,2295 v1(2955,2265) ; v1(2875,2060) 2785,2060 ; NT1.2@3085,1795 3168.86,1795 R29.1@3190,1773.86 ; TP14.1@3105,2395 3052.5,2395 3040,2382.5 3040,2250 2953.7,2163.7 2888.7,2163.7 2785,2060
  Top Layer w15: 2086.98,2473.02 2086.98,2508.02 2163.95,2585 v1(2175,2585) ; v1(2145,2265) 2193.5,2265 C47.2@2194.57,2266.06 ; v1(3180,3515) 3207.33,3515 3225,3497.33 3225,3482.77 3247.77,3460 3240,3452.23 3240,3400 v1(3220,3380)
  Top Layer w20: C12.2@838.56,3498.47 C12.2@845,3492.03 ; v1(2150,3350) 2165.39,3334.61 2165.39,3296.5 2191.89,3270 U7.2@2232.76,3270 v1(2285,3270) ; C45.2@2908.62,2265 v1(2955,2265)
  Top Layer w25: C12.2@838.56,3498.47 v1@876.53,3498.47 ; v1(855,1125) 860,1120 U1.2@860,1067.24
  Top Layer w30: C11.2@778.56,3498.47 C12.2@838.56,3498.47
  other v1: 796.88,74.36 695,75 745,75 964,75 695,130 745,130 796.88,134.36 963.12,134.36 695,180 745,180 962,192 796.88,194.36 695,235 745,235 695,290 745,290 695,345 745,345 695,400 745,400 695,455 745,455 700,995 575,1130 195,1155 325,1175 375,1175 255,1225 325,1225 375,1225 605,1285 195,1305 580,1350 545,1615 4550,1615 1560,1650 1700,1650 1930,1650 2070,1650 2300,1650 2440,1650 2670,1650 2810,1650 3040,1650 3185,1650 3410,1650 3550,1650 495,1665 545,1665 4550,1670 4610,1670 1560,1705 1700,1705 1810,1705 1870,1705 1930,1705 2070,1705 2300,1705 2440,1705 2670,1705 2810,1705 3040,1705 3185,1705 3239,1705 3295,1705 3410,1705 3550,1705 1600,1745 1655,1745 2340,1745 2395,1745 2710,1745 2765,1745 3450,1745 3505,1745 615,1755 660,1755 705,1755 745.63,1755 4345,1755 4390,1755 4435,1755 4480,1755 1750,1760 1810,1760 2020,1765 2070,1765 3040,1765 3095,1765 3295,1765 3355,1765 2897.13,1955.94 2530,2060 2605,2060 3045,2140 2270,2145 1890,2270 3205,2365 3205,2410 1615,2500 1675,2500 3445,2500 3505,2500 1555,2555 1725,2555 3385,2555 3555,2555 1555,2605 1725,2605 3385,2605 3555,2605 1555,2655 1725,2655 2620,2655 3385,2655 3555,2655 1840,2690 1885,2690 1930,2690 1975,2690 2025,2690 2075,2690 2255,2710 3035,2720 3080,2720 3125,2720 3175,2720 3220,2720 3270,2720 2785,2735 2785,2795 1005,2950 2900,3210 805,3265 855,3265 910,3265 970,3265 1020,3265 1070,3265 3465,3265 3300,3267.17 1235,3285 1290,3285 1345,3285 1830,3325 1200,3345 1900,3430 1040,3438.55 885,3490 2900,3490 3055,3490 720,3500 1015,3570.99 1060,3570.99 720,3620 1330,3680 1200,3685 775,3730 865,3730 2870,4465 2340,4510 2405,4540 2509.06,4552.44 2870,4630 2065,4670 2120,4670
  other v2: 125,135 170,135 215,135 260,135 580,135 625,135 125,180 170,180 215,180 625,180 125,225 170,225 125,270 170,270 125,315 170,315 125,360 170,360 125,405 170,405 215,405 625,405 125,450 170,450 215,450 260,450 580,450 625,450 4360,3260 4400,3260 4440,3260 4875,3265 4915,3265 4955,3265 4995,3265 4360,3300 4875,3305 4915,3305 4955,3305 4995,3305 4360,3340 4875,3345 4915,3345 4955,3345 4995,3345 4875,3385 4915,3385 4955,3385 4995,3385 4875,3425 4915,3425 4955,3425 4995,3425 4875,3465 4915,3465 4955,3465 4995,3465 4875,3515 4915,3515 4955,3515 4995,3515 4875,3555 4915,3555 4955,3555 4995,3555 4875,3595 4915,3595 4955,3595 4995,3595 4875,3635 4915,3635 4955,3635 4995,3635 4360,3640 4875,3675 4915,3675 4955,3675 4995,3675 4360,3680 4875,3715 4915,3715 4955,3715 4995,3715 4360,3720 4400,3720 4440,3720
  other v3: 2556.06,2326.06 2506.06,2376.06 2606.06,2376.06 2556.06,2426.06 1022.3,3486.35 1057.74,3486.35 1022.3,3533.59 1057.74,3533.59
NetC1_1: C1.1 L1.1 L3.1 R1.1 R3.2 U1.5 | length 274
  Top Layer w25: U1.5@897.41,972.75 897.41,771.18 R3.2@948.58,720
NetC2_1: C2.1 L1.2 L2.1 L3.2 L4.1 R1.2 R2.1 | length 1073.1
  MidLayer2 w100: v1(1140,170) 1950,170 2030,250 v1(2030,340) v1(2030,400)
  other v1: 1200,170
NetC9_1: C9.1 D1.1 L5.1 TP5.1 U2.10 | length 341.7
  Top Layer w30: v1(1120,3300) C9.1@1120.02,3348.47
  MidLayer2 w15: v1(880,3428.47) 991.53,3428.47 v1(1120,3300)
NetC9_2: C9.2 U2.1 | length 59.4
  Top Layer w10: C9.2@1120.02,3411.46 1120.73,3412.17 U2.1@1120.73,3470.6
NetC10_1: C10.1 U2.4 | length 95.4
  Top Layer w10: U2.4@1120.73,3529.65 1161.2,3529.65 C10.1@1200.02,3568.47
NetC11_1: C11.1 R8.2 | length 59.1
  Top Layer w20: R8.2@777.07,3619.97 777.07,3562.96 C11.1@778.56,3561.46
NetC12_1: C12.1 R8.1 U2.8 | length 201.5
  Top Layer w10: C12.1@838.56,3561.46 860.03,3540 885,3540 892,3533 892,3532.54 912.89,3511.65 913.35,3511.65 915.03,3509.97 U2.8@959.31,3509.97 ; R8.1@838.56,3618.47 R8.1@840.06,3619.97
  Top Layer w20: C12.1@838.56,3561.46 R8.1@838.56,3618.47
NetC14_1: C14.1 TP9.1 U3.2 | length 193.9
  Top Layer w20: TP9.1@2240,4570 2260,4590 2301.46,4590 2332.8,4621.34 U3.2@2412.6,4621.34
NetC16_1: C16.1 TP10.1 U4.2 | length 376.1
  Top Layer w20: TP10.1@480,1325 480,1355 525,1400 680,1400 691.5,1388.5 C16.1@691.5,1350 691.34,1349.84 U4.2@691.34,1277.4
NetC18_1: C18.1 TP11.1 U5.2 | length 328.5
  Top Layer w15: U5.2@2966.02,2052.4 2966.02,2124.84 C18.1@2966.18,2125 2980,2138.82 2980,2153.54 3116.46,2290 TP11.1@3145,2290
NetC28_1: C28.1 D2.2 U6.1 | length 208.4
  Top Layer w10: D2.2@2326.06,2545.39 D2.2@2337.56,2533.9 ; C28.1@2337.56,2480.51 2409.49,2480.51 2445.04,2444.96 U6.1@2461.57,2444.96
  Top Layer w20: C28.1@2337.56,2480.51 D2.2@2337.56,2533.9
NetC29_1: C29.1 R12.2 U6.29 | length 264.4
  Top Layer w10: U6.29@2546.22,2470.55 2546.22,2528.78
  Top Layer w20: R12.2@2476.06,2662.6 2476.06,2606.06 2496.06,2586.06 C29.1@2556.06,2586.06
  Top Layer w30: 2546.22,2528.78 2546.22,2576.22 C29.1@2556.06,2586.06
NetC31_1: C31.1 D2.1 U6.30 | length 298.5
  Top Layer w10: D2.1@2326.06,2655.63 2377.99,2655.63 C31.1@2406.06,2627.56 2526.54,2507.09 U6.30@2526.54,2470.55
NetC31_2: C31.2 C38.1 L7.2 L9.1 Q2.1 Q2.2 Q2.3 Q4.1 Q4.2 Q4.3 Q6.1 Q6.2 Q6.3 Q7.5 Q9.5 R33.2 TP16.1 U6.32 | length 1641
  Top Layer w10: v1(2130,2480) 2095,2445 2095,2260 v1(2145,2210) ; C31.2@2406.06,2564.57 2406.06,2516.06 v1(2405,2515) 2449.45,2470.55 U6.32@2487.17,2470.55
  Top Layer w20: v1(2145,2210) 2190.63,2210 R33.2@2194.57,2206.06
  MidLayer2 w15: v1(2130,2480) 2130,2515
  MidLayer2 w20: v1(1395,2300) 1510,2415 1720,2415 1820,2515 2130,2515 v1(2405,2515)
NetC32_1: C32.1 D3.1 U6.27 | length 309.7
  Top Layer w10: U6.27@2585.59,2470.55 2585.59,2495.59 2665,2575 2665,2596.5 C32.1@2706.06,2637.56 2733.33,2664.83 2782.42,2664.83 D3.1@2786.06,2661.18
NetC32_2: C32.2 C33.1 L6.1 L8.2 Q1.1 Q1.2 Q1.3 Q3.1 Q3.2 Q3.3 Q5.1 Q5.2 Q5.3 Q8.5 Q10.5 R31.2 TP15.1 U6.25 | length 1632.3
  Top Layer w10: U6.25@2624.96,2470.55 2660.55,2470.55 v1(2705,2515) 2705,2573.5 C32.2@2706.06,2574.57 ; v1(2955,2210) 3005,2260 v1(3005,2480)
  Top Layer w20: R31.2@2907.56,2206.06 2911.5,2210 v1(2955,2210)
  MidLayer2 w15: v1(3005,2480) 3005,2515
  MidLayer2 w20: v1(2705,2515) 3005,2515 3290,2515 3380,2425 3590,2425 v1(3715,2300)
NetC33_2: C33.2 R23.2 | length 101.8
  Top Layer w35: R23.2@4727.09,1600 4731.5,1604.41 C33.2@4731.5,1700
NetC38_2: C38.2 R26.2 | length 101.8
  Top Layer w35: C38.2@368.5,1700 368.5,1604.41 R26.2@372.91,1600
NetC41_2: C41.2 U6.18 | length 224.5
  Top Layer w10: U6.18@2650.55,2326.85 2683.15,2326.85 2786.06,2223.94 C41.2@2786.06,2177.56
NetC42_2: C42.2 U6.14 | length 112.5
  Top Layer w10: U6.14@2585.59,2281.57 2585.59,2229.41 2597.28,2217.72 2597.28,2186.35 C42.2@2606.06,2177.56
NetC43_1: C43.1 R27.1 U6.20 | length 209.8
  Top Layer w10: U6.20@2650.55,2366.22 2703.78,2366.22 2745.43,2324.57 C43.1@2786.06,2324.57
  Top Layer w20: C43.1@2786.06,2324.57 R27.1@2843.07,2324.57
NetC43_2: C43.2 R34.1 U6.21 | length 205.2
  Top Layer w10: U6.21@2650.55,2385.91 2711.67,2385.91 2722.57,2375 2773.5,2375 2784.41,2385.91 C43.2@2786.06,2387.56
  Top Layer w20: C43.2@2784.41,2385.91 R34.1@2844.41,2385.91
NetC44_1: C44.1 R28.1 U6.5 | length 219.8
  Top Layer w10: C44.1@2316.06,2324.57 2354.57,2324.57 2396.22,2366.22 U6.5@2461.57,2366.22
  Top Layer w20: R28.1@2257.56,2326.06 C44.1@2314.57,2326.06
NetC44_2: C44.2 R32.1 U6.4 | length 208.1
  Top Layer w10: C44.2@2316.06,2387.56 2323.62,2380 2382.43,2380 2388.33,2385.91 U6.4@2461.57,2385.91
  Top Layer w20: R32.1@2257.56,2386.06 C44.2@2314.57,2386.06
NetC45_1: C45.1 R31.1 U6.19 | length 287.3
  Top Layer w10: U6.19@2650.55,2346.54 2693.46,2346.54 2773.94,2266.06 C45.1@2844.57,2266.06
  Top Layer w20: R31.1@2844.57,2206.06 C45.1@2844.57,2266.06
NetC46_1: C46.1 U6.7 | length 202.8
  Top Layer w10: C46.1@2316.06,2207.56 2344.61,2236.1 2344.61,2249.61 2421.85,2326.85 U6.7@2461.57,2326.85
NetC47_1: C47.1 R33.1 U6.6 | length 297.3
  Top Layer w10: C47.1@2257.56,2266.06 2326.06,2266.06 2406.54,2346.54 U6.6@2461.57,2346.54
  Top Layer w20: R33.1@2257.56,2206.06 C47.1@2257.56,2266.06
NetC48_2: C48.2 C49.2 R37.1 R39.1 R39.2 R40.2 U6.9 | length 654.3
  Top Layer w10: R39.2@2343.15,2006.06 2363.15,2026.06 R39.2@2365,2027.91 ; C49.2@2414.57,2149.05 C49.2@2416.06,2147.56 ; C48.2@2414.57,2206.06 2414.57,2264.57 2431.57,2281.57 U6.9@2487.17,2281.57
  Top Layer w20: R37.1@2156.06,2064.57 2219.69,2064.57 R39.1@2228.98,2055.28 2278.19,2006.06 R39.2@2343.15,2006.06 ; R39.2@2363.15,2026.06 R40.2@2414.57,2026.06 ; R39.2@2365,2027.91 2365,2135.12 2377.44,2147.56 C49.2@2416.06,2147.56 ; C49.2@2414.57,2149.05 C48.2@2414.57,2206.06
NetC49_1: C49.1 R38.2 | length 60
  Top Layer w20: C49.1@2416.06,2084.57 R38.2@2476.06,2084.57
NetC50_1: C50.1 D4.3 Q15.1 R44.2 | length 232.2
  Top Layer w15: R44.2@2931.69,4574.07 2944.51,4586.89 D4.3@3010.2,4586.89 3078.7,4586.89 Q15.1@3092.8,4572.8
  Top Layer w20: C50.1@2931.69,4514.07 R44.2@2931.69,4574.07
